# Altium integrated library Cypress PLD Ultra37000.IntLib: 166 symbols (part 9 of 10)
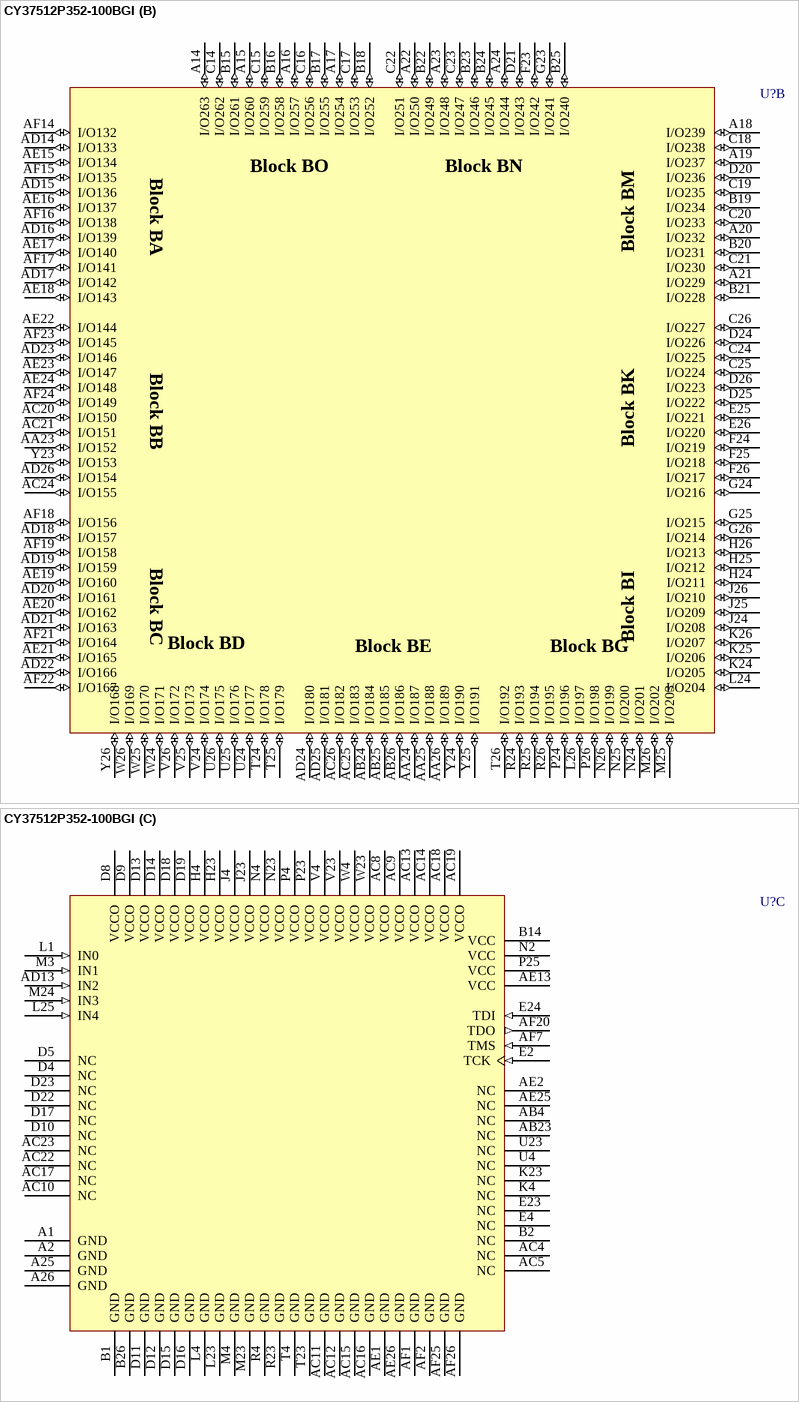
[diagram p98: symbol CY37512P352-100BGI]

## CY37512P352-100BGI
designator U?
Ultra37000 5V, ISR High-Performance CPLD
footprint BG352 (BGA, 388-Leads, Body 35x35mm, Pitch 1.27mm)
3D model CY37512P352-BG352 (388-Ball Ball Grid Array 1.27 mm Pitch)
part A pins: A3 I/O19 (io), A4 I/O15 (io), A5 I/O13 (io), A6 I/O34 (io), A7 I/O31 (io), A8 I/O28 (io), A9 I/O25 (io), A10 I/O10 (io), A11 I/O7 (io), A12 I/O4 (io), A13 I/O1 (io), AA1 I/O74 (io), AA2 I/O75 (io), AA3 I/O76 (io), AA4 I/O111 (io), AB1 I/O77 (io), AB2 I/O78 (io), AB3 I/O79 (io), AC1 I/O81 (io), AC2 I/O80 (io), AC3 I/O108 (io), AC6 I/O112 (io), AC7 I/O113 (io), AD1 I/O109 (io), AD2 I/O82 (io), AD3 I/O83 (io), AD4 I/O117 (io), AD5 I/O97 (io), AD6 I/O100 (io), AD7 I/O102 (io), AD8 I/O105 (io), AD9 I/O120 (io), AD10 I/O123 (io), AD11 I/O126 (io), AD12 I/O129 (io), AE3 I/O115 (io), AE4 I/O116 (io), AE5 I/O119 (io), AE6 I/O98 (io), AE7 I/O101 (io), AE8 I/O103 (io), AE9 I/O106 (io), AE10 I/O121 (io), AE11 I/O124 (io), AE12 I/O127 (io), AE14 I/O130 (io), AF3 I/O114 (io), AF4 I/O118 (io), AF5 I/O96 (io), AF6 I/O99 (io), AF8 I/O104 (io), AF9 I/O107 (io), AF10 I/O122 (io), AF11 I/O125 (io), AF12 I/O128 (io), AF13 I/O131 (io), B3 I/O18 (io), B4 I/O17 (io), B5 I/O14 (io), B6 I/O35 (io), B7 I/O32 (io), B8 I/O29 (io), B9 I/O26 (io), B10 I/O11 (io), B11 I/O8 (io), B12 I/O5 (io), B13 I/O2 (io), C1 I/O23 (io), C2 I/O38 (io), C3 I/O37 (io), C4 I/O16 (io), C5 I/O12 (io), C6 I/O33 (io), C7 I/O30 (io), C8 I/O27 (io), C9 I/O24 (io), C10 I/O9 (io), C11 I/O6 (io), C12 I/O3 (io), C13 I/O0 (io), D1 I/O39 (io), D2 I/O40 (io), D3 I/O36 (io), D6 I/O21 (io), D7 I/O20 (io), E1 I/O42 (io), E3 I/O41 (io), F1 I/O45 (io), F2 I/O44 (io), F3 I/O43 (io), F4 I/O22 (io), G1 I/O48 (io), G2 I/O47 (io), G3 I/O46 (io), G4 I/O63 (io), H1 I/O49 (io), H2 I/O50 (io), H3 I/O51 (io), J1 I/O52 (io), J2 I/O53 (io), J3 I/O54 (io), K1 I/O55 (io), K2 I/O56 (io), K3 I/O57 (io), L2 I/O59 (io), L3 I/O58 (io), M1 I/O61 (io), M2 I/O60 (io), N1 I/O64 (io), N3 I/O62 (io), P1 I/O65 (io), P2 I/O66 (io), P3 I/O67 (io), R1 I/O68 (io), R2 I/O69 (io), R3 I/O70 (io), T1 I/O71 (io), T2 I/O84 (io), T3 I/O85 (io), U1 I/O88 (io), U2 I/O87 (io), U3 I/O86 (io), V1 I/O91 (io), V2 I/O90 (io), V3 I/O89 (io), W1 I/O94 (io), W2 I/O93 (io), W3 I/O92 (io), Y1 I/O95 (io), Y2 I/O72 (io), Y3 I/O73 (io), Y4 I/O110 (io)
part B pins: A14 I/O263 (io), A15 I/O260 (io), A16 I/O257 (io), A17 I/O254 (io), A18 I/O239 (io), A19 I/O237 (io), A20 I/O232 (io), A21 I/O229 (io), A22 I/O250 (io), A23 I/O248 (io), A24 I/O244 (io), AA23 I/O152 (io), AA24 I/O187 (io), AA25 I/O188 (io), AA26 I/O189 (io), AB24 I/O184 (io), AB25 I/O185 (io), AB26 I/O186 (io), AC20 I/O150 (io), AC21 I/O151 (io), AC24 I/O155 (io), AC25 I/O183 (io), AC26 I/O182 (io), AD14 I/O133 (io), AD15 I/O136 (io), AD16 I/O139 (io), AD17 I/O142 (io), AD18 I/O157 (io), AD19 I/O159 (io), AD20 I/O161 (io), AD21 I/O163 (io), AD22 I/O166 (io), AD23 I/O146 (io), AD24 I/O180 (io), AD25 I/O181 (io), AD26 I/O154 (io), AE15 I/O134 (io), AE16 I/O137 (io), AE17 I/O140 (io), AE18 I/O143 (io), AE19 I/O160 (io), AE20 I/O162 (io), AE21 I/O165 (io), AE22 I/O144 (io), AE23 I/O147 (io), AE24 I/O148 (io), AF14 I/O132 (io), AF15 I/O135 (io), AF16 I/O138 (io), AF17 I/O141 (io), AF18 I/O156 (io), AF19 I/O158 (io), AF21 I/O164 (io), AF22 I/O167 (io), AF23 I/O145 (io), AF24 I/O149 (io), B15 I/O261 (io), B16 I/O258 (io), B17 I/O255 (io), B18 I/O252 (io), B19 I/O234 (io), B20 I/O231 (io), B21 I/O228 (io), B22 I/O249 (io), B23 I/O246 (io), B24 I/O245 (io), B25 I/O240 (io), C14 I/O262 (io), C15 I/O259 (io), C16 I/O256 (io), C17 I/O253 (io), C18 I/O238 (io), C19 I/O235 (io), C20 I/O233 (io), C21 I/O230 (io), C22 I/O251 (io), C23 I/O247 (io), C24 I/O225 (io), C25 I/O224 (io), C26 I/O227 (io), D20 I/O236 (io), D21 I/O243 (io), D24 I/O226 (io), D25 I/O222 (io), D26 I/O223 (io), E25 I/O221 (io), E26 I/O220 (io), F23 I/O242 (io), F24 I/O219 (io), F25 I/O218 (io), F26 I/O217 (io), G23 I/O241 (io), G24 I/O216 (io), G25 I/O215 (io), G26 I/O214 (io), H24 I/O211 (io), H25 I/O212 (io), H26 I/O213 (io), J24 I/O208 (io), J25 I/O209 (io), J26 I/O210 (io), K24 I/O205 (io), K25 I/O206 (io), K26 I/O207 (io), L24 I/O204 (io), L26 I/O197 (io), M25 I/O203 (io), M26 I/O202 (io), N24 I/O201 (io), N25 I/O200 (io), N26 I/O199 (io), P24 I/O196 (io), P26 I/O198 (io), R24 I/O193 (io), R25 I/O194 (io), R26 I/O195 (io), T24 I/O178 (io), T25 I/O179 (io), T26 I/O192 (io), U24 I/O177 (io), U25 I/O176 (io), U26 I/O175 (io), V24 I/O174 (io), V25 I/O173 (io), V26 I/O172 (io), W24 I/O171 (io), W25 I/O170 (io), W26 I/O169 (io), Y23 I/O153 (io), Y24 I/O190 (io), Y25 I/O191 (io), Y26 I/O168 (io)
part C pins: A1 GND (power), A2 GND (power), A25 GND (power), A26 GND (power), AB4 NC, AB23 NC, AC4 NC, AC5 NC, AC8 VCCO (power), AC9 VCCO (power), AC10 NC, AC11 GND (power), AC12 GND (power), AC13 VCCO (power), AC14 VCCO (power), AC15 GND (power), AC16 GND (power), AC17 NC, AC18 VCCO (power), AC19 VCCO (power), AC22 NC, AC23 NC, AD13 IN2 (in), AE1 GND (power), AE2 NC, AE13 VCC (power), AE25 NC, AE26 GND (power), AF1 GND (power), AF2 GND (power), AF7 TMS (in), AF20 TDO (out), AF25 GND (power), AF26 GND (power), B1 GND (power), B2 NC, B14 VCC (power), B26 GND (power), D4 NC, D5 NC, D8 VCCO (power), D9 VCCO (power), D10 NC, D11 GND (power), D12 GND (power), D13 VCCO (power), D14 VCCO (power), D15 GND (power), D16 GND (power), D17 NC, D18 VCCO (power), D19 VCCO (power), D22 NC, D23 NC, E2 TCK (in), E4 NC, E23 NC, E24 TDI (in), H4 VCCO (power), H23 VCCO (power), J4 VCCO (power), J23 VCCO (power), K4 NC, K23 NC, L1 IN0 (in), L4 GND (power), L23 GND (power), L25 IN4 (in), M3 IN1 (in), M4 GND (power), M23 GND (power), M24 IN3 (in), N2 VCC (power), N4 VCCO (power), N23 VCCO (power), P4 VCCO (power), P23 VCCO (power), P25 VCC (power), R4 GND (power), R23 GND (power), T4 GND (power), T23 GND (power), U4 NC, U23 NC, V4 VCCO (power), V23 VCCO (power), W4 VCCO (power), W23 VCCO (power)

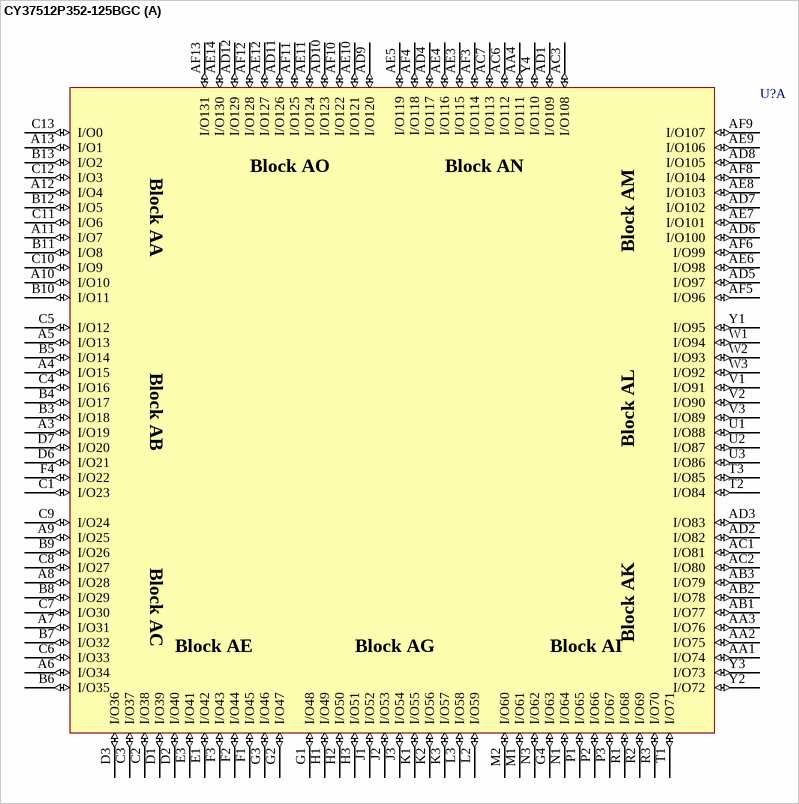
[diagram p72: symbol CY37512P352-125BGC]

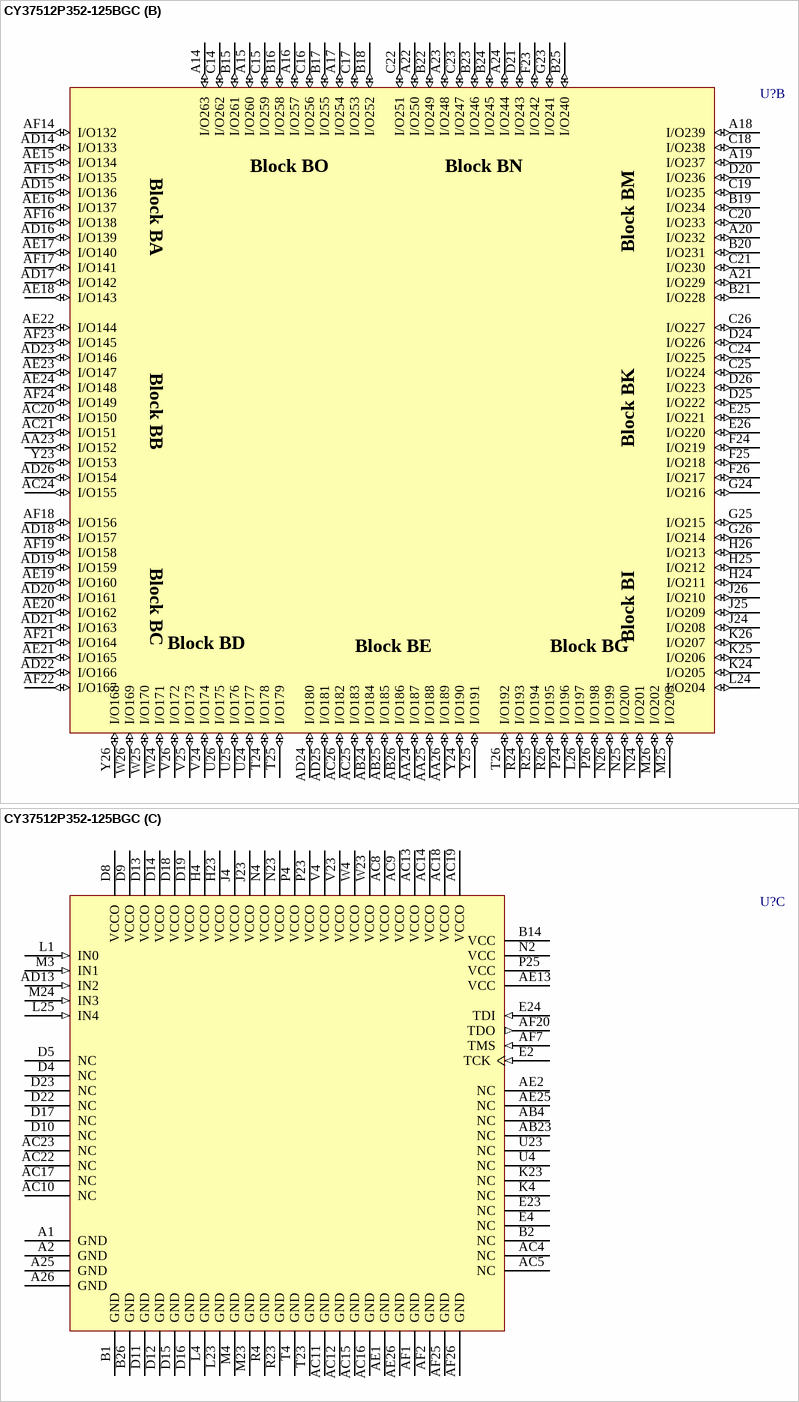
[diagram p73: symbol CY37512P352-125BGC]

## CY37512P352-125BGC
designator U?
Ultra37000 5V, ISR High-Performance CPLD
footprint BG352 (BGA, 388-Leads, Body 35x35mm, Pitch 1.27mm)
3D model CY37512P352-BG352 (388-Ball Ball Grid Array 1.27 mm Pitch)
part A pins: A3 I/O19 (io), A4 I/O15 (io), A5 I/O13 (io), A6 I/O34 (io), A7 I/O31 (io), A8 I/O28 (io), A9 I/O25 (io), A10 I/O10 (io), A11 I/O7 (io), A12 I/O4 (io), A13 I/O1 (io), AA1 I/O74 (io), AA2 I/O75 (io), AA3 I/O76 (io), AA4 I/O111 (io), AB1 I/O77 (io), AB2 I/O78 (io), AB3 I/O79 (io), AC1 I/O81 (io), AC2 I/O80 (io), AC3 I/O108 (io), AC6 I/O112 (io), AC7 I/O113 (io), AD1 I/O109 (io), AD2 I/O82 (io), AD3 I/O83 (io), AD4 I/O117 (io), AD5 I/O97 (io), AD6 I/O100 (io), AD7 I/O102 (io), AD8 I/O105 (io), AD9 I/O120 (io), AD10 I/O123 (io), AD11 I/O126 (io), AD12 I/O129 (io), AE3 I/O115 (io), AE4 I/O116 (io), AE5 I/O119 (io), AE6 I/O98 (io), AE7 I/O101 (io), AE8 I/O103 (io), AE9 I/O106 (io), AE10 I/O121 (io), AE11 I/O124 (io), AE12 I/O127 (io), AE14 I/O130 (io), AF3 I/O114 (io), AF4 I/O118 (io), AF5 I/O96 (io), AF6 I/O99 (io), AF8 I/O104 (io), AF9 I/O107 (io), AF10 I/O122 (io), AF11 I/O125 (io), AF12 I/O128 (io), AF13 I/O131 (io), B3 I/O18 (io), B4 I/O17 (io), B5 I/O14 (io), B6 I/O35 (io), B7 I/O32 (io), B8 I/O29 (io), B9 I/O26 (io), B10 I/O11 (io), B11 I/O8 (io), B12 I/O5 (io), B13 I/O2 (io), C1 I/O23 (io), C2 I/O38 (io), C3 I/O37 (io), C4 I/O16 (io), C5 I/O12 (io), C6 I/O33 (io), C7 I/O30 (io), C8 I/O27 (io), C9 I/O24 (io), C10 I/O9 (io), C11 I/O6 (io), C12 I/O3 (io), C13 I/O0 (io), D1 I/O39 (io), D2 I/O40 (io), D3 I/O36 (io), D6 I/O21 (io), D7 I/O20 (io), E1 I/O42 (io), E3 I/O41 (io), F1 I/O45 (io), F2 I/O44 (io), F3 I/O43 (io), F4 I/O22 (io), G1 I/O48 (io), G2 I/O47 (io), G3 I/O46 (io), G4 I/O63 (io), H1 I/O49 (io), H2 I/O50 (io), H3 I/O51 (io), J1 I/O52 (io), J2 I/O53 (io), J3 I/O54 (io), K1 I/O55 (io), K2 I/O56 (io), K3 I/O57 (io), L2 I/O59 (io), L3 I/O58 (io), M1 I/O61 (io), M2 I/O60 (io), N1 I/O64 (io), N3 I/O62 (io), P1 I/O65 (io), P2 I/O66 (io), P3 I/O67 (io), R1 I/O68 (io), R2 I/O69 (io), R3 I/O70 (io), T1 I/O71 (io), T2 I/O84 (io), T3 I/O85 (io), U1 I/O88 (io), U2 I/O87 (io), U3 I/O86 (io), V1 I/O91 (io), V2 I/O90 (io), V3 I/O89 (io), W1 I/O94 (io), W2 I/O93 (io), W3 I/O92 (io), Y1 I/O95 (io), Y2 I/O72 (io), Y3 I/O73 (io), Y4 I/O110 (io)
part B pins: A14 I/O263 (io), A15 I/O260 (io), A16 I/O257 (io), A17 I/O254 (io), A18 I/O239 (io), A19 I/O237 (io), A20 I/O232 (io), A21 I/O229 (io), A22 I/O250 (io), A23 I/O248 (io), A24 I/O244 (io), AA23 I/O152 (io), AA24 I/O187 (io), AA25 I/O188 (io), AA26 I/O189 (io), AB24 I/O184 (io), AB25 I/O185 (io), AB26 I/O186 (io), AC20 I/O150 (io), AC21 I/O151 (io), AC24 I/O155 (io), AC25 I/O183 (io), AC26 I/O182 (io), AD14 I/O133 (io), AD15 I/O136 (io), AD16 I/O139 (io), AD17 I/O142 (io), AD18 I/O157 (io), AD19 I/O159 (io), AD20 I/O161 (io), AD21 I/O163 (io), AD22 I/O166 (io), AD23 I/O146 (io), AD24 I/O180 (io), AD25 I/O181 (io), AD26 I/O154 (io), AE15 I/O134 (io), AE16 I/O137 (io), AE17 I/O140 (io), AE18 I/O143 (io), AE19 I/O160 (io), AE20 I/O162 (io), AE21 I/O165 (io), AE22 I/O144 (io), AE23 I/O147 (io), AE24 I/O148 (io), AF14 I/O132 (io), AF15 I/O135 (io), AF16 I/O138 (io), AF17 I/O141 (io), AF18 I/O156 (io), AF19 I/O158 (io), AF21 I/O164 (io), AF22 I/O167 (io), AF23 I/O145 (io), AF24 I/O149 (io), B15 I/O261 (io), B16 I/O258 (io), B17 I/O255 (io), B18 I/O252 (io), B19 I/O234 (io), B20 I/O231 (io), B21 I/O228 (io), B22 I/O249 (io), B23 I/O246 (io), B24 I/O245 (io), B25 I/O240 (io), C14 I/O262 (io), C15 I/O259 (io), C16 I/O256 (io), C17 I/O253 (io), C18 I/O238 (io), C19 I/O235 (io), C20 I/O233 (io), C21 I/O230 (io), C22 I/O251 (io), C23 I/O247 (io), C24 I/O225 (io), C25 I/O224 (io), C26 I/O227 (io), D20 I/O236 (io), D21 I/O243 (io), D24 I/O226 (io), D25 I/O222 (io), D26 I/O223 (io), E25 I/O221 (io), E26 I/O220 (io), F23 I/O242 (io), F24 I/O219 (io), F25 I/O218 (io), F26 I/O217 (io), G23 I/O241 (io), G24 I/O216 (io), G25 I/O215 (io), G26 I/O214 (io), H24 I/O211 (io), H25 I/O212 (io), H26 I/O213 (io), J24 I/O208 (io), J25 I/O209 (io), J26 I/O210 (io), K24 I/O205 (io), K25 I/O206 (io), K26 I/O207 (io), L24 I/O204 (io), L26 I/O197 (io), M25 I/O203 (io), M26 I/O202 (io), N24 I/O201 (io), N25 I/O200 (io), N26 I/O199 (io), P24 I/O196 (io), P26 I/O198 (io), R24 I/O193 (io), R25 I/O194 (io), R26 I/O195 (io), T24 I/O178 (io), T25 I/O179 (io), T26 I/O192 (io), U24 I/O177 (io), U25 I/O176 (io), U26 I/O175 (io), V24 I/O174 (io), V25 I/O173 (io), V26 I/O172 (io), W24 I/O171 (io), W25 I/O170 (io), W26 I/O169 (io), Y23 I/O153 (io), Y24 I/O190 (io), Y25 I/O191 (io), Y26 I/O168 (io)
part C pins: A1 GND (power), A2 GND (power), A25 GND (power), A26 GND (power), AB4 NC, AB23 NC, AC4 NC, AC5 NC, AC8 VCCO (power), AC9 VCCO (power), AC10 NC, AC11 GND (power), AC12 GND (power), AC13 VCCO (power), AC14 VCCO (power), AC15 GND (power), AC16 GND (power), AC17 NC, AC18 VCCO (power), AC19 VCCO (power), AC22 NC, AC23 NC, AD13 IN2 (in), AE1 GND (power), AE2 NC, AE13 VCC (power), AE25 NC, AE26 GND (power), AF1 GND (power), AF2 GND (power), AF7 TMS (in), AF20 TDO (out), AF25 GND (power), AF26 GND (power), B1 GND (power), B2 NC, B14 VCC (power), B26 GND (power), D4 NC, D5 NC, D8 VCCO (power), D9 VCCO (power), D10 NC, D11 GND (power), D12 GND (power), D13 VCCO (power), D14 VCCO (power), D15 GND (power), D16 GND (power), D17 NC, D18 VCCO (power), D19 VCCO (power), D22 NC, D23 NC, E2 TCK (in), E4 NC, E23 NC, E24 TDI (in), H4 VCCO (power), H23 VCCO (power), J4 VCCO (power), J23 VCCO (power), K4 NC, K23 NC, L1 IN0 (in), L4 GND (power), L23 GND (power), L25 IN4 (in), M3 IN1 (in), M4 GND (power), M23 GND (power), M24 IN3 (in), N2 VCC (power), N4 VCCO (power), N23 VCCO (power), P4 VCCO (power), P23 VCCO (power), P25 VCC (power), R4 GND (power), R23 GND (power), T4 GND (power), T23 GND (power), U4 NC, U23 NC, V4 VCCO (power), V23 VCCO (power), W4 VCCO (power), W23 VCCO (power)

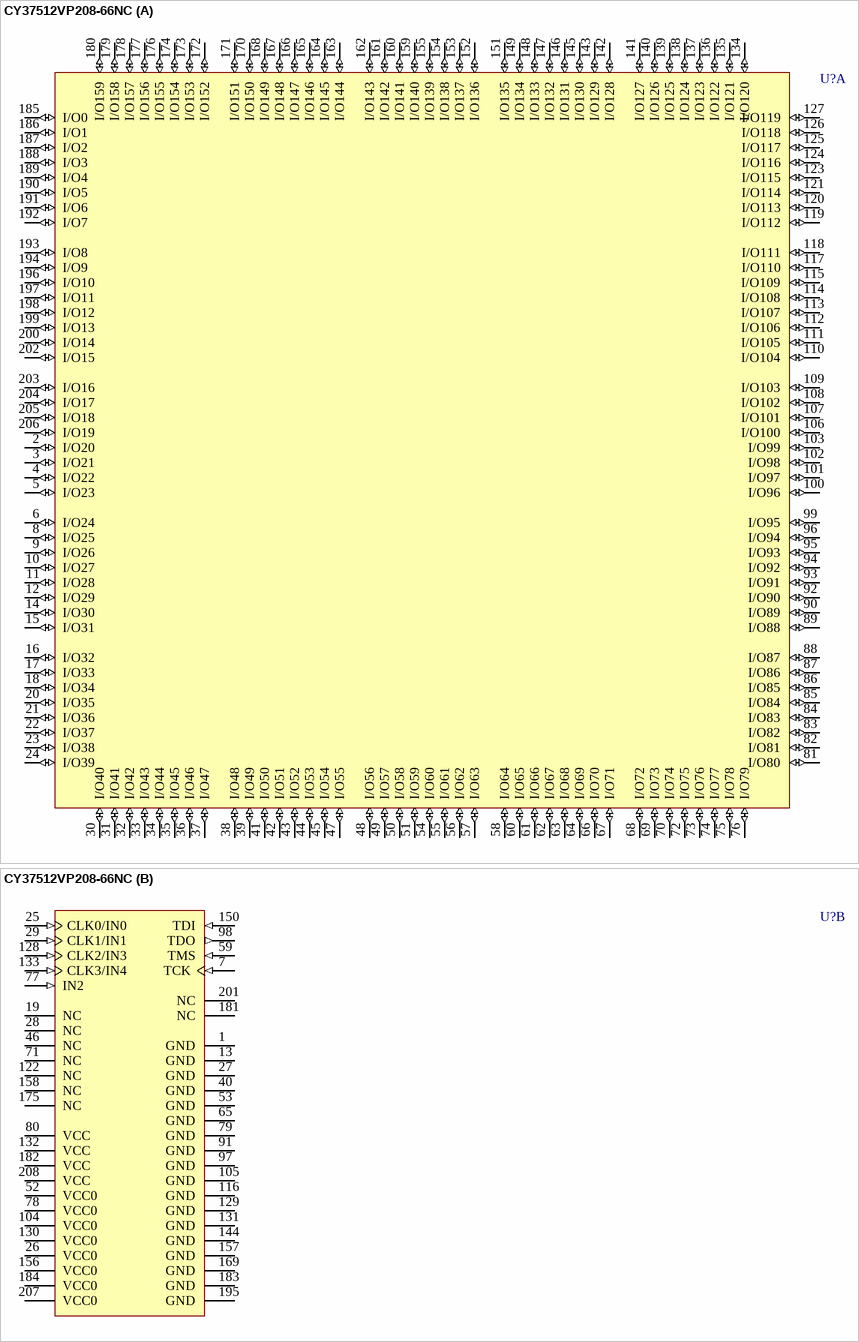
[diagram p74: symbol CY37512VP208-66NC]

## CY37512VP208-66NC
designator U?
Ultra37000 3.3V, ISR High-Performance CPLD
footprint N208_N (Shrink QFP, 208-Leads, Body 28x28mm, Pitch 0.5mm, IPC Medium Density)
footprint N208_L (Shrink QFP, 208-Leads, Body 28x28mm, Pitch 0.5mm, IPC High Density)
footprint N208_M (Shrink QFP, 208-Leads, Body 28x28mm, Pitch 0.5mm, IPC Low Density)
3D model CY37512VP208-N208 (208-Pin Plastic Shrink Quad Flat Pack 0.5 mm Pitch)
part A pins: 2 I/O20 (io), 3 I/O21 (io), 4 I/O22 (io), 5 I/O23 (io), 6 I/O24 (io), 8 I/O25 (io), 9 I/O26 (io), 10 I/O27 (io), 11 I/O28 (io), 12 I/O29 (io), 14 I/O30 (io), 15 I/O31 (io), 16 I/O32 (io), 17 I/O33 (io), 18 I/O34 (io), 20 I/O35 (io), 21 I/O36 (io), 22 I/O37 (io), 23 I/O38 (io), 24 I/O39 (io), 30 I/O40 (io), 31 I/O41 (io), 32 I/O42 (io), 33 I/O43 (io), 34 I/O44 (io), 35 I/O45 (io), 36 I/O46 (io), 37 I/O47 (io), 38 I/O48 (io), 39 I/O49 (io), 41 I/O50 (io), 42 I/O51 (io), 43 I/O52 (io), 44 I/O53 (io), 45 I/O54 (io), 47 I/O55 (io), 48 I/O56 (io), 49 I/O57 (io), 50 I/O58 (io), 51 I/O59 (io), 54 I/O60 (io), 55 I/O61 (io), 56 I/O62 (io), 57 I/O63 (io), 58 I/O64 (io), 60 I/O65 (io), 61 I/O66 (io), 62 I/O67 (io), 63 I/O68 (io), 64 I/O69 (io), 66 I/O70 (io), 67 I/O71 (io), 68 I/O72 (io), 69 I/O73 (io), 70 I/O74 (io), 72 I/O75 (io), 73 I/O76 (io), 74 I/O77 (io), 75 I/O78 (io), 76 I/O79 (io), 81 I/O80 (io), 82 I/O81 (io), 83 I/O82 (io), 84 I/O83 (io), 85 I/O84 (io), 86 I/O85 (io), 87 I/O86 (io), 88 I/O87 (io), 89 I/O88 (io), 90 I/O89 (io), 92 I/O90 (io), 93 I/O91 (io), 94 I/O92 (io), 95 I/O93 (io), 96 I/O94 (io), 99 I/O95 (io), 100 I/O96 (io), 101 I/O97 (io), 102 I/O98 (io), 103 I/O99 (io), 106 I/O100 (io), 107 I/O101 (io), 108 I/O102 (io), 109 I/O103 (io), 110 I/O104 (io), 111 I/O105 (io), 112 I/O106 (io), 113 I/O107 (io), 114 I/O108 (io), 115 I/O109 (io), 117 I/O110 (io), 118 I/O111 (io), 119 I/O112 (io), 120 I/O113 (io), 121 I/O114 (io), 123 I/O115 (io), 124 I/O116 (io), 125 I/O117 (io), 126 I/O118 (io), 127 I/O119 (io), 134 I/O120 (io), 135 I/O121 (io), 136 I/O122 (io), 137 I/O123 (io), 138 I/O124 (io), 139 I/O125 (io), 140 I/O126 (io), 141 I/O127 (io), 142 I/O128 (io), 143 I/O129 (io), 145 I/O130 (io), 146 I/O131 (io), 147 I/O132 (io), 148 I/O133 (io), 149 I/O134 (io), 151 I/O135 (io), 152 I/O136 (io), 153 I/O137 (io), 154 I/O138 (io), 155 I/O139 (io), 159 I/O140 (io), 160 I/O141 (io), 161 I/O142 (io), 162 I/O143 (io), 163 I/O144 (io), 164 I/O145 (io), 165 I/O146 (io), 166 I/O147 (io), 167 I/O148 (io), 168 I/O149 (io), 170 I/O150 (io), 171 I/O151 (io), 172 I/O152 (io), 173 I/O153 (io), 174 I/O154 (io), 176 I/O155 (io), 177 I/O156 (io), 178 I/O157 (io), 179 I/O158 (io), 180 I/O159 (io), 185 I/O0 (io), 186 I/O1 (io), 187 I/O2 (io), 188 I/O3 (io), 189 I/O4 (io), 190 I/O5 (io), 191 I/O6 (io), 192 I/O7 (io), 193 I/O8 (io), 194 I/O9 (io), 196 I/O10 (io), 197 I/O11 (io), 198 I/O12 (io), 199 I/O13 (io), 200 I/O14 (io), 202 I/O15 (io), 203 I/O16 (io), 204 I/O17 (io), 205 I/O18 (io), 206 I/O19 (io)
part B pins: 1 GND (power), 7 TCK (in), 13 GND (power), 19 NC, 25 CLK0/IN0 (in), 26 VCC0 (power), 27 GND (power), 28 NC, 29 CLK1/IN1 (in), 40 GND (power), 46 NC, 52 VCC0 (power), 53 GND (power), 59 TMS (in), 65 GND (power), 71 NC, 77 IN2 (in), 78 VCC0 (power), 79 GND (power), 80 VCC (power), 91 GND (power), 97 GND (power), 98 TDO (out), 104 VCC0 (power), 105 GND (power), 116 GND (power), 122 NC, 128 CLK2/IN3 (in), 129 GND (power), 130 VCC0 (power), 131 GND (power), 132 VCC (power), 133 CLK3/IN4 (in), 144 GND (power), 150 TDI (in), 156 VCC0 (power), 157 GND (power), 158 NC, 169 GND (power), 175 NC, 181 NC, 182 VCC (power), 183 GND (power), 184 VCC0 (power), 195 GND (power), 201 NC, 207 VCC0 (power), 208 VCC (power)

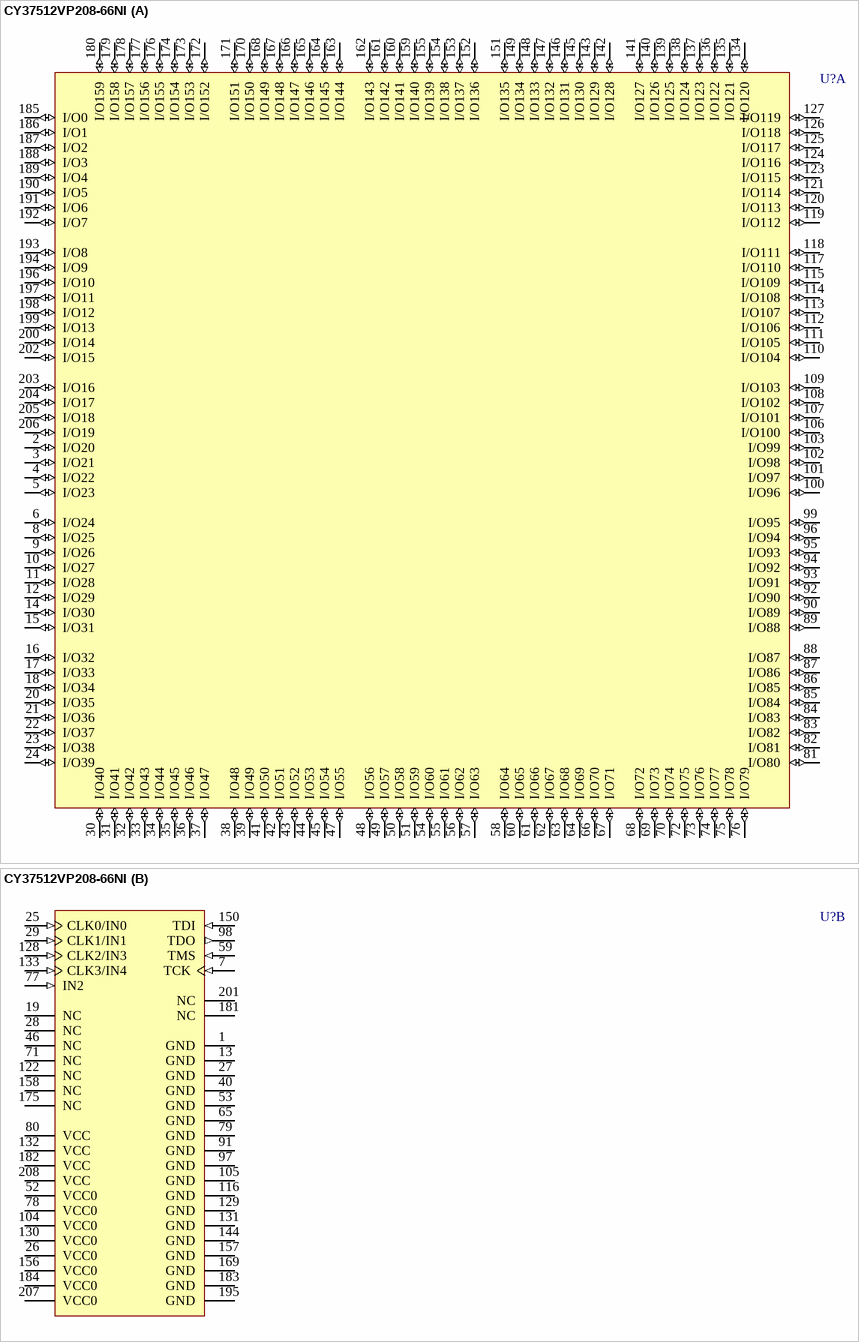
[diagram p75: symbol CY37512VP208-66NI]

## CY37512VP208-66NI
designator U?
Ultra37000 3.3V, ISR High-Performance CPLD
footprint N208_N (Shrink QFP, 208-Leads, Body 28x28mm, Pitch 0.5mm, IPC Medium Density)
footprint N208_L (Shrink QFP, 208-Leads, Body 28x28mm, Pitch 0.5mm, IPC High Density)
footprint N208_M (Shrink QFP, 208-Leads, Body 28x28mm, Pitch 0.5mm, IPC Low Density)
3D model CY37512VP208-N208 (208-Pin Plastic Shrink Quad Flat Pack 0.5 mm Pitch)
part A pins: 2 I/O20 (io), 3 I/O21 (io), 4 I/O22 (io), 5 I/O23 (io), 6 I/O24 (io), 8 I/O25 (io), 9 I/O26 (io), 10 I/O27 (io), 11 I/O28 (io), 12 I/O29 (io), 14 I/O30 (io), 15 I/O31 (io), 16 I/O32 (io), 17 I/O33 (io), 18 I/O34 (io), 20 I/O35 (io), 21 I/O36 (io), 22 I/O37 (io), 23 I/O38 (io), 24 I/O39 (io), 30 I/O40 (io), 31 I/O41 (io), 32 I/O42 (io), 33 I/O43 (io), 34 I/O44 (io), 35 I/O45 (io), 36 I/O46 (io), 37 I/O47 (io), 38 I/O48 (io), 39 I/O49 (io), 41 I/O50 (io), 42 I/O51 (io), 43 I/O52 (io), 44 I/O53 (io), 45 I/O54 (io), 47 I/O55 (io), 48 I/O56 (io), 49 I/O57 (io), 50 I/O58 (io), 51 I/O59 (io), 54 I/O60 (io), 55 I/O61 (io), 56 I/O62 (io), 57 I/O63 (io), 58 I/O64 (io), 60 I/O65 (io), 61 I/O66 (io), 62 I/O67 (io), 63 I/O68 (io), 64 I/O69 (io), 66 I/O70 (io), 67 I/O71 (io), 68 I/O72 (io), 69 I/O73 (io), 70 I/O74 (io), 72 I/O75 (io), 73 I/O76 (io), 74 I/O77 (io), 75 I/O78 (io), 76 I/O79 (io), 81 I/O80 (io), 82 I/O81 (io), 83 I/O82 (io), 84 I/O83 (io), 85 I/O84 (io), 86 I/O85 (io), 87 I/O86 (io), 88 I/O87 (io), 89 I/O88 (io), 90 I/O89 (io), 92 I/O90 (io), 93 I/O91 (io), 94 I/O92 (io), 95 I/O93 (io), 96 I/O94 (io), 99 I/O95 (io), 100 I/O96 (io), 101 I/O97 (io), 102 I/O98 (io), 103 I/O99 (io), 106 I/O100 (io), 107 I/O101 (io), 108 I/O102 (io), 109 I/O103 (io), 110 I/O104 (io), 111 I/O105 (io), 112 I/O106 (io), 113 I/O107 (io), 114 I/O108 (io), 115 I/O109 (io), 117 I/O110 (io), 118 I/O111 (io), 119 I/O112 (io), 120 I/O113 (io), 121 I/O114 (io), 123 I/O115 (io), 124 I/O116 (io), 125 I/O117 (io), 126 I/O118 (io), 127 I/O119 (io), 134 I/O120 (io), 135 I/O121 (io), 136 I/O122 (io), 137 I/O123 (io), 138 I/O124 (io), 139 I/O125 (io), 140 I/O126 (io), 141 I/O127 (io), 142 I/O128 (io), 143 I/O129 (io), 145 I/O130 (io), 146 I/O131 (io), 147 I/O132 (io), 148 I/O133 (io), 149 I/O134 (io), 151 I/O135 (io), 152 I/O136 (io), 153 I/O137 (io), 154 I/O138 (io), 155 I/O139 (io), 159 I/O140 (io), 160 I/O141 (io), 161 I/O142 (io), 162 I/O143 (io), 163 I/O144 (io), 164 I/O145 (io), 165 I/O146 (io), 166 I/O147 (io), 167 I/O148 (io), 168 I/O149 (io), 170 I/O150 (io), 171 I/O151 (io), 172 I/O152 (io), 173 I/O153 (io), 174 I/O154 (io), 176 I/O155 (io), 177 I/O156 (io), 178 I/O157 (io), 179 I/O158 (io), 180 I/O159 (io), 185 I/O0 (io), 186 I/O1 (io), 187 I/O2 (io), 188 I/O3 (io), 189 I/O4 (io), 190 I/O5 (io), 191 I/O6 (io), 192 I/O7 (io), 193 I/O8 (io), 194 I/O9 (io), 196 I/O10 (io), 197 I/O11 (io), 198 I/O12 (io), 199 I/O13 (io), 200 I/O14 (io), 202 I/O15 (io), 203 I/O16 (io), 204 I/O17 (io), 205 I/O18 (io), 206 I/O19 (io)
part B pins: 1 GND (power), 7 TCK (in), 13 GND (power), 19 NC, 25 CLK0/IN0 (in), 26 VCC0 (power), 27 GND (power), 28 NC, 29 CLK1/IN1 (in), 40 GND (power), 46 NC, 52 VCC0 (power), 53 GND (power), 59 TMS (in), 65 GND (power), 71 NC, 77 IN2 (in), 78 VCC0 (power), 79 GND (power), 80 VCC (power), 91 GND (power), 97 GND (power), 98 TDO (out), 104 VCC0 (power), 105 GND (power), 116 GND (power), 122 NC, 128 CLK2/IN3 (in), 129 GND (power), 130 VCC0 (power), 131 GND (power), 132 VCC (power), 133 CLK3/IN4 (in), 144 GND (power), 150 TDI (in), 156 VCC0 (power), 157 GND (power), 158 NC, 169 GND (power), 175 NC, 181 NC, 182 VCC (power), 183 GND (power), 184 VCC0 (power), 195 GND (power), 201 NC, 207 VCC0 (power), 208 VCC (power)

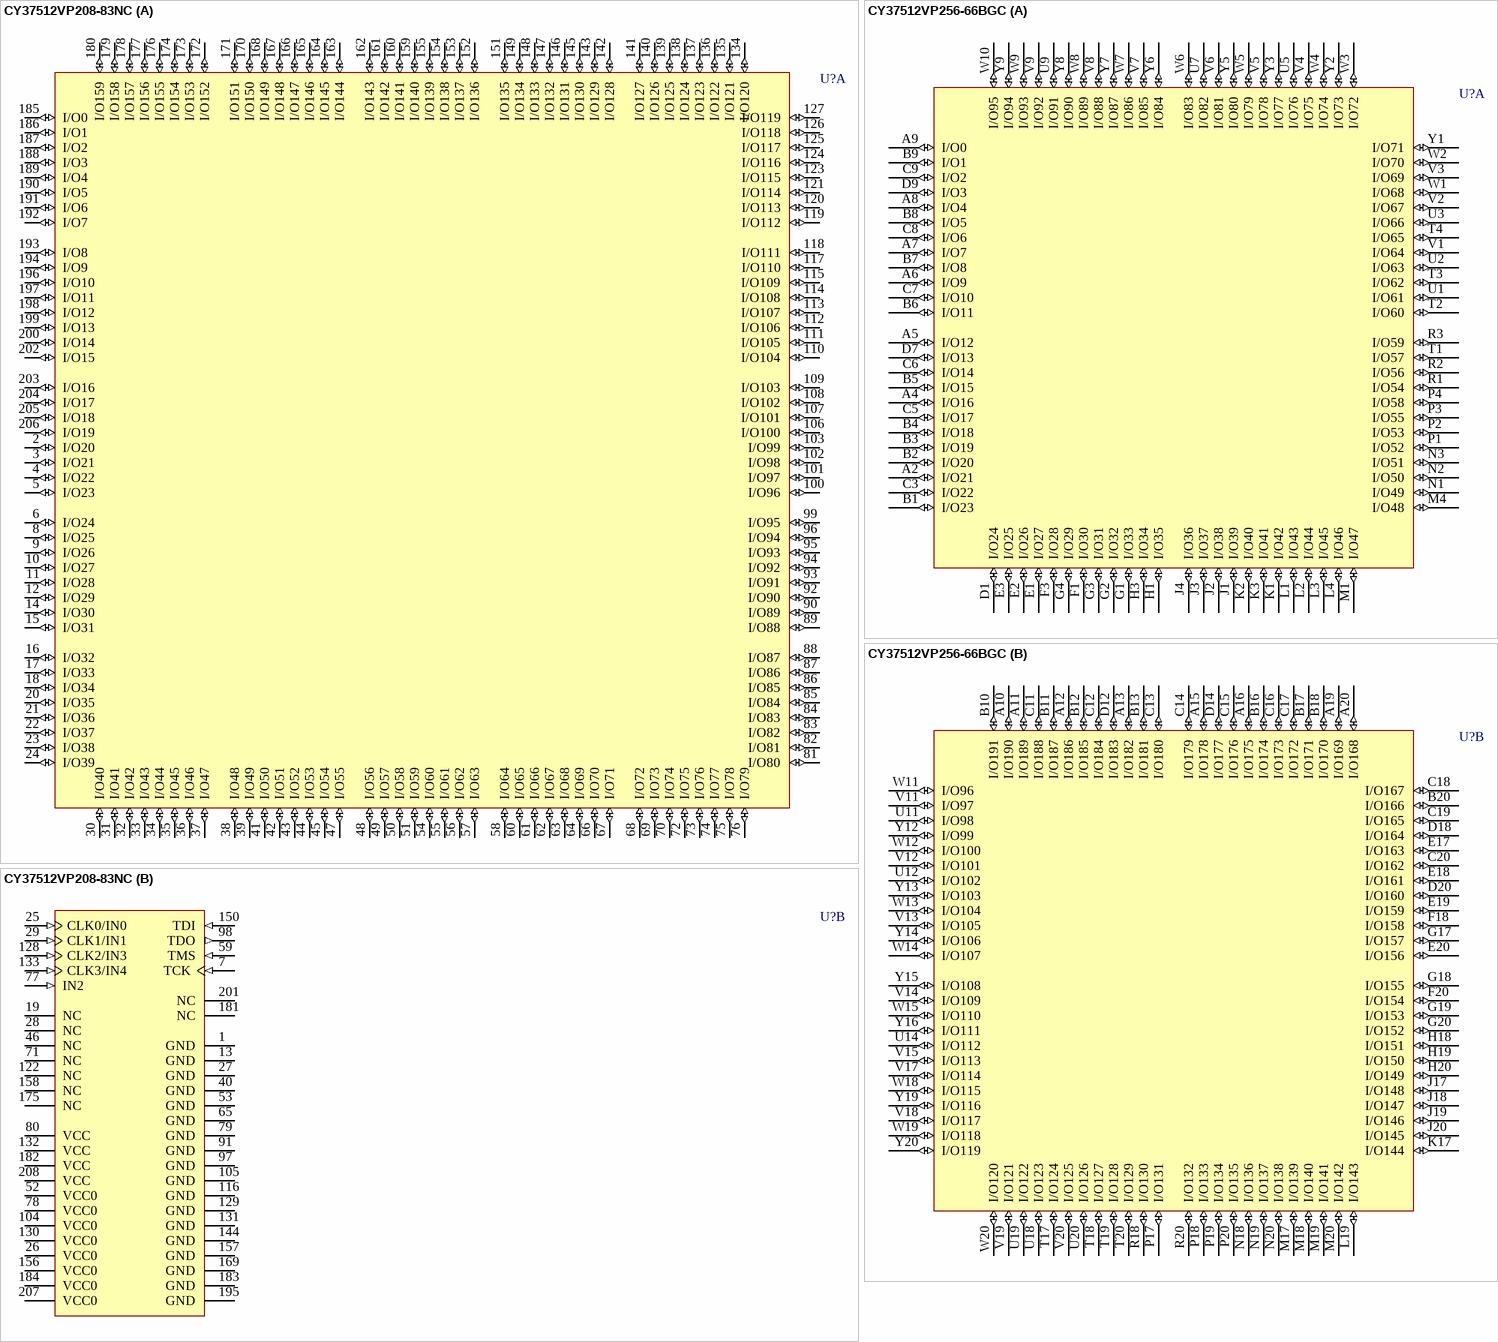
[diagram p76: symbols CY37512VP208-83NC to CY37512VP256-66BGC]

## CY37512VP208-83NC
designator U?
Ultra37000 3.3V, ISR High-Performance CPLD
footprint N208_N (Shrink QFP, 208-Leads, Body 28x28mm, Pitch 0.5mm, IPC Medium Density)
footprint N208_L (Shrink QFP, 208-Leads, Body 28x28mm, Pitch 0.5mm, IPC High Density)
footprint N208_M (Shrink QFP, 208-Leads, Body 28x28mm, Pitch 0.5mm, IPC Low Density)
3D model CY37512VP208-N208 (208-Pin Plastic Shrink Quad Flat Pack 0.5 mm Pitch)
part A pins: 2 I/O20 (io), 3 I/O21 (io), 4 I/O22 (io), 5 I/O23 (io), 6 I/O24 (io), 8 I/O25 (io), 9 I/O26 (io), 10 I/O27 (io), 11 I/O28 (io), 12 I/O29 (io), 14 I/O30 (io), 15 I/O31 (io), 16 I/O32 (io), 17 I/O33 (io), 18 I/O34 (io), 20 I/O35 (io), 21 I/O36 (io), 22 I/O37 (io), 23 I/O38 (io), 24 I/O39 (io), 30 I/O40 (io), 31 I/O41 (io), 32 I/O42 (io), 33 I/O43 (io), 34 I/O44 (io), 35 I/O45 (io), 36 I/O46 (io), 37 I/O47 (io), 38 I/O48 (io), 39 I/O49 (io), 41 I/O50 (io), 42 I/O51 (io), 43 I/O52 (io), 44 I/O53 (io), 45 I/O54 (io), 47 I/O55 (io), 48 I/O56 (io), 49 I/O57 (io), 50 I/O58 (io), 51 I/O59 (io), 54 I/O60 (io), 55 I/O61 (io), 56 I/O62 (io), 57 I/O63 (io), 58 I/O64 (io), 60 I/O65 (io), 61 I/O66 (io), 62 I/O67 (io), 63 I/O68 (io), 64 I/O69 (io), 66 I/O70 (io), 67 I/O71 (io), 68 I/O72 (io), 69 I/O73 (io), 70 I/O74 (io), 72 I/O75 (io), 73 I/O76 (io), 74 I/O77 (io), 75 I/O78 (io), 76 I/O79 (io), 81 I/O80 (io), 82 I/O81 (io), 83 I/O82 (io), 84 I/O83 (io), 85 I/O84 (io), 86 I/O85 (io), 87 I/O86 (io), 88 I/O87 (io), 89 I/O88 (io), 90 I/O89 (io), 92 I/O90 (io), 93 I/O91 (io), 94 I/O92 (io), 95 I/O93 (io), 96 I/O94 (io), 99 I/O95 (io), 100 I/O96 (io), 101 I/O97 (io), 102 I/O98 (io), 103 I/O99 (io), 106 I/O100 (io), 107 I/O101 (io), 108 I/O102 (io), 109 I/O103 (io), 110 I/O104 (io), 111 I/O105 (io), 112 I/O106 (io), 113 I/O107 (io), 114 I/O108 (io), 115 I/O109 (io), 117 I/O110 (io), 118 I/O111 (io), 119 I/O112 (io), 120 I/O113 (io), 121 I/O114 (io), 123 I/O115 (io), 124 I/O116 (io), 125 I/O117 (io), 126 I/O118 (io), 127 I/O119 (io), 134 I/O120 (io), 135 I/O121 (io), 136 I/O122 (io), 137 I/O123 (io), 138 I/O124 (io), 139 I/O125 (io), 140 I/O126 (io), 141 I/O127 (io), 142 I/O128 (io), 143 I/O129 (io), 145 I/O130 (io), 146 I/O131 (io), 147 I/O132 (io), 148 I/O133 (io), 149 I/O134 (io), 151 I/O135 (io), 152 I/O136 (io), 153 I/O137 (io), 154 I/O138 (io), 155 I/O139 (io), 159 I/O140 (io), 160 I/O141 (io), 161 I/O142 (io), 162 I/O143 (io), 163 I/O144 (io), 164 I/O145 (io), 165 I/O146 (io), 166 I/O147 (io), 167 I/O148 (io), 168 I/O149 (io), 170 I/O150 (io), 171 I/O151 (io), 172 I/O152 (io), 173 I/O153 (io), 174 I/O154 (io), 176 I/O155 (io), 177 I/O156 (io), 178 I/O157 (io), 179 I/O158 (io), 180 I/O159 (io), 185 I/O0 (io), 186 I/O1 (io), 187 I/O2 (io), 188 I/O3 (io), 189 I/O4 (io), 190 I/O5 (io), 191 I/O6 (io), 192 I/O7 (io), 193 I/O8 (io), 194 I/O9 (io), 196 I/O10 (io), 197 I/O11 (io), 198 I/O12 (io), 199 I/O13 (io), 200 I/O14 (io), 202 I/O15 (io), 203 I/O16 (io), 204 I/O17 (io), 205 I/O18 (io), 206 I/O19 (io)
part B pins: 1 GND (power), 7 TCK (in), 13 GND (power), 19 NC, 25 CLK0/IN0 (in), 26 VCC0 (power), 27 GND (power), 28 NC, 29 CLK1/IN1 (in), 40 GND (power), 46 NC, 52 VCC0 (power), 53 GND (power), 59 TMS (in), 65 GND (power), 71 NC, 77 IN2 (in), 78 VCC0 (power), 79 GND (power), 80 VCC (power), 91 GND (power), 97 GND (power), 98 TDO (out), 104 VCC0 (power), 105 GND (power), 116 GND (power), 122 NC, 128 CLK2/IN3 (in), 129 GND (power), 130 VCC0 (power), 131 GND (power), 132 VCC (power), 133 CLK3/IN4 (in), 144 GND (power), 150 TDI (in), 156 VCC0 (power), 157 GND (power), 158 NC, 169 GND (power), 175 NC, 181 NC, 182 VCC (power), 183 GND (power), 184 VCC0 (power), 195 GND (power), 201 NC, 207 VCC0 (power), 208 VCC (power)

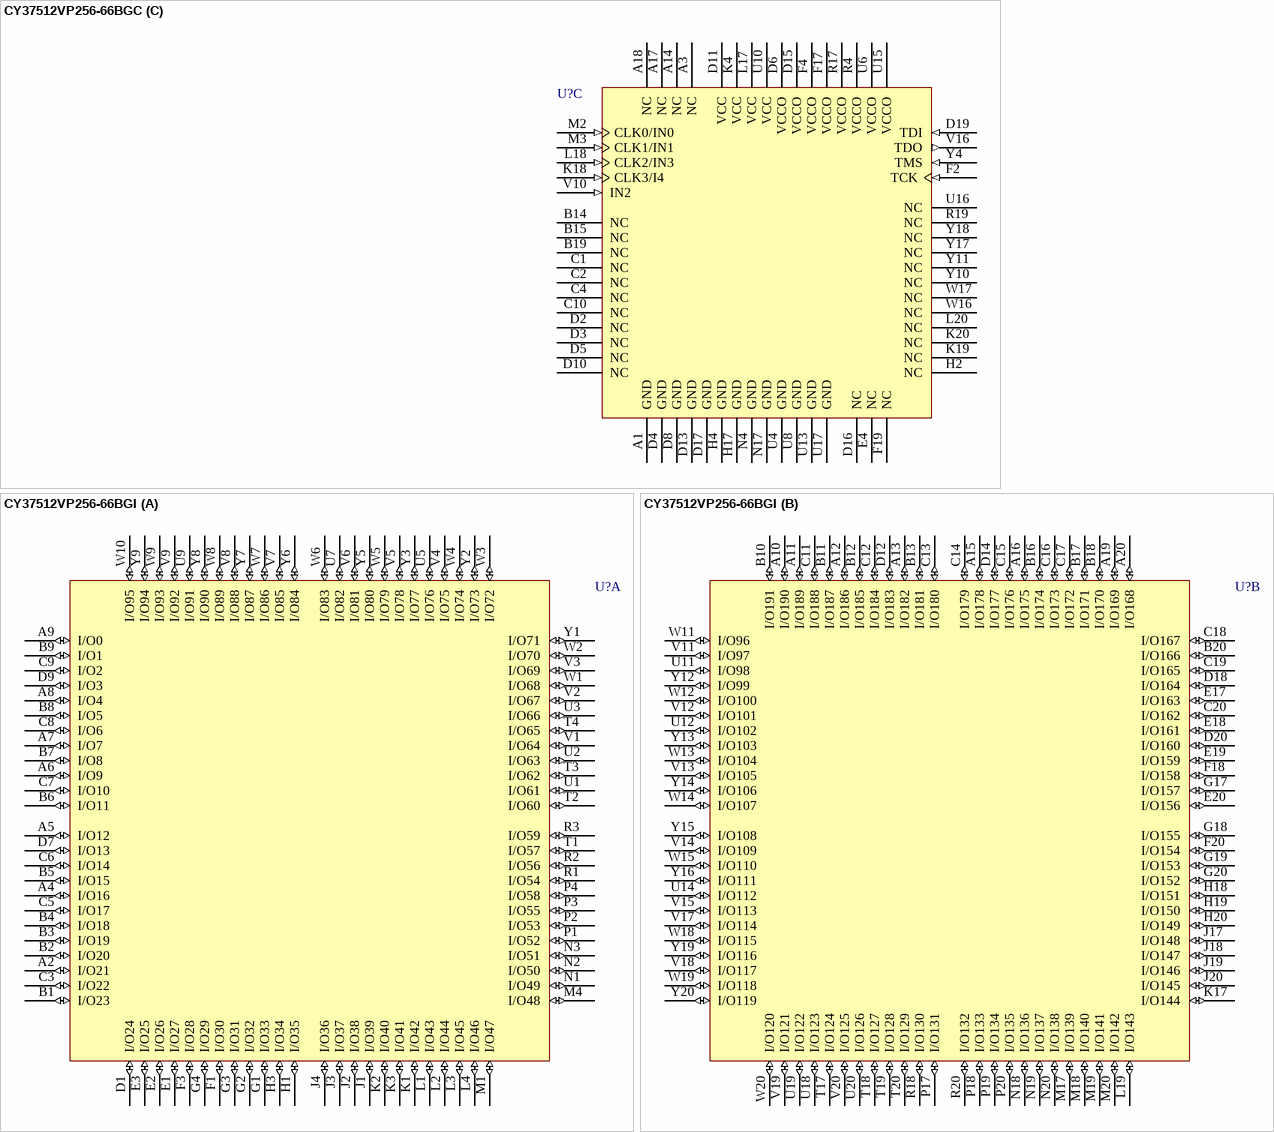
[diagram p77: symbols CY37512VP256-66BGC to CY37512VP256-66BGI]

## CY37512VP256-66BGC
designator U?
Ultra37000 3.3V, ISR High-Performance CPLD
footprint BG256 (BGA, 292-Leads, Body 27x27mm, Pitch 1.27mm)
3D model CY37512VP256-BG256 (292-Ball Ball Grid Array 1.27 mm Pitch)
part A pins: A2 I/O21 (io), A4 I/O16 (io), A5 I/O12 (io), A6 I/O9 (io), A7 I/O7 (io), A8 I/O4 (io), A9 I/O0 (io), B1 I/O23 (io), B2 I/O20 (io), B3 I/O19 (io), B4 I/O18 (io), B5 I/O15 (io), B6 I/O11 (io), B7 I/O8 (io), B8 I/O5 (io), B9 I/O1 (io), C3 I/O22 (io), C5 I/O17 (io), C6 I/O14 (io), C7 I/O10 (io), C8 I/O6 (io), C9 I/O2 (io), D1 I/O24 (io), D7 I/O13 (io), D9 I/O3 (io), E1 I/O27 (io), E2 I/O26 (io), E3 I/O25 (io), F1 I/O30 (io), F3 I/O28 (io), G1 I/O33 (io), G2 I/O32 (io), G3 I/O31 (io), G4 I/O29 (io), H1 I/O35 (io), H3 I/O34 (io), J1 I/O39 (io), J2 I/O38 (io), J3 I/O37 (io), J4 I/O36 (io), K1 I/O42 (io), K2 I/O40 (io), K3 I/O41 (io), L1 I/O43 (io), L2 I/O44 (io), L3 I/O45 (io), L4 I/O46 (io), M1 I/O47 (io), M4 I/O48 (io), N1 I/O49 (io), N2 I/O50 (io), N3 I/O51 (io), P1 I/O52 (io), P2 I/O53 (io), P3 I/O55 (io), P4 I/O58 (io), R1 I/O54 (io), R2 I/O56 (io), R3 I/O59 (io), T1 I/O57 (io), T2 I/O60 (io), T3 I/O62 (io), T4 I/O65 (io), U1 I/O61 (io), U2 I/O63 (io), U3 I/O66 (io), U5 I/O76 (io), U7 I/O82 (io), U9 I/O91 (io), V1 I/O64 (io), V2 I/O67 (io), V3 I/O69 (io), V4 I/O75 (io), V5 I/O78 (io), V6 I/O81 (io), V7 I/O85 (io), V8 I/O88 (io), V9 I/O92 (io), W1 I/O68 (io), W2 I/O70 (io), W3 I/O72 (io), W4 I/O74 (io), W5 I/O79 (io), W6 I/O83 (io), W7 I/O86 (io), W8 I/O89 (io), W9 I/O93 (io), W10 I/O95 (io), Y1 I/O71 (io), Y2 I/O73 (io), Y3 I/O77 (io), Y5 I/O80 (io), Y6 I/O84 (io), Y7 I/O87 (io), Y8 I/O90 (io), Y9 I/O94 (io)
part B pins: A10 I/O190 (io), A11 I/O189 (io), A12 I/O186 (io), A13 I/O182 (io), A15 I/O178 (io), A16 I/O175 (io), A19 I/O169 (io), A20 I/O168 (io), B10 I/O191 (io), B11 I/O187 (io), B12 I/O185 (io), B13 I/O181 (io), B16 I/O174 (io), B17 I/O171 (io), B18 I/O170 (io), B20 I/O166 (io), C11 I/O188 (io), C12 I/O184 (io), C13 I/O180 (io), C14 I/O179 (io), C15 I/O176 (io), C16 I/O173 (io), C17 I/O172 (io), C18 I/O167 (io), C19 I/O165 (io), C20 I/O162 (io), D12 I/O183 (io), D14 I/O177 (io), D18 I/O164 (io), D20 I/O160 (io), E17 I/O163 (io), E18 I/O161 (io), E19 I/O159 (io), E20 I/O156 (io), F18 I/O158 (io), F20 I/O154 (io), G17 I/O157 (io), G18 I/O155 (io), G19 I/O153 (io), G20 I/O152 (io), H18 I/O151 (io), H19 I/O150 (io), H20 I/O149 (io), J17 I/O148 (io), J18 I/O147 (io), J19 I/O146 (io), J20 I/O145 (io), K17 I/O144 (io), L19 I/O143 (io), M17 I/O139 (io), M18 I/O140 (io), M19 I/O141 (io), M20 I/O142 (io), N18 I/O136 (io), N19 I/O137 (io), N20 I/O138 (io), P17 I/O131 (io), P18 I/O133 (io), P19 I/O134 (io), P20 I/O135 (io), R18 I/O130 (io), R20 I/O132 (io), T17 I/O124 (io), T18 I/O127 (io), T19 I/O128 (io), T20 I/O129 (io), U11 I/O98 (io), U12 I/O102 (io), U14 I/O112 (io), U18 I/O123 (io), U19 I/O122 (io), U20 I/O126 (io), V11 I/O97 (io), V12 I/O101 (io), V13 I/O105 (io), V14 I/O109 (io), V15 I/O113 (io), V17 I/O114 (io), V18 I/O117 (io), V19 I/O121 (io), V20 I/O125 (io), W11 I/O96 (io), W12 I/O100 (io), W13 I/O104 (io), W14 I/O107 (io), W15 I/O110 (io), W18 I/O115 (io), W19 I/O118 (io), W20 I/O120 (io), Y12 I/O99 (io), Y13 I/O103 (io), Y14 I/O106 (io), Y15 I/O108 (io), Y16 I/O111 (io), Y19 I/O116 (io), Y20 I/O119 (io)
part C pins: A1 GND (power), A3 NC, A14 NC, A17 NC, A18 NC, B14 NC, B15 NC, B19 NC, C1 NC, C2 NC, C4 NC, C10 NC, D2 NC, D3 NC, D4 GND (power), D5 NC, D6 VCCO (power), D8 GND (power), D10 NC, D11 VCC (power), D13 GND (power), D15 VCCO (power), D16 NC, D17 GND (power), D19 TDI (in), E4 NC, F2 TCK (in), F4 VCCO (power), F17 VCCO (power), F19 NC, H2 NC, H4 GND (power), H17 GND (power), K4 VCC (power), K18 CLK3/I4 (in), K19 NC, K20 NC, L17 VCC (power), L18 CLK2/IN3 (in), L20 NC, M2 CLK0/IN0 (in), M3 CLK1/IN1 (in), N4 GND (power), N17 GND (power), R4 VCCO (power), R17 VCCO (power), R19 NC, U4 GND (power), U6 VCCO (power), U8 GND (power), U10 VCC (power), U13 GND (power), U15 VCCO (power), U16 NC, U17 GND (power), V10 IN2 (in), V16 TDO (out), W16 NC, W17 NC, Y4 TMS (in), Y10 NC, Y11 NC, Y17 NC, Y18 NC

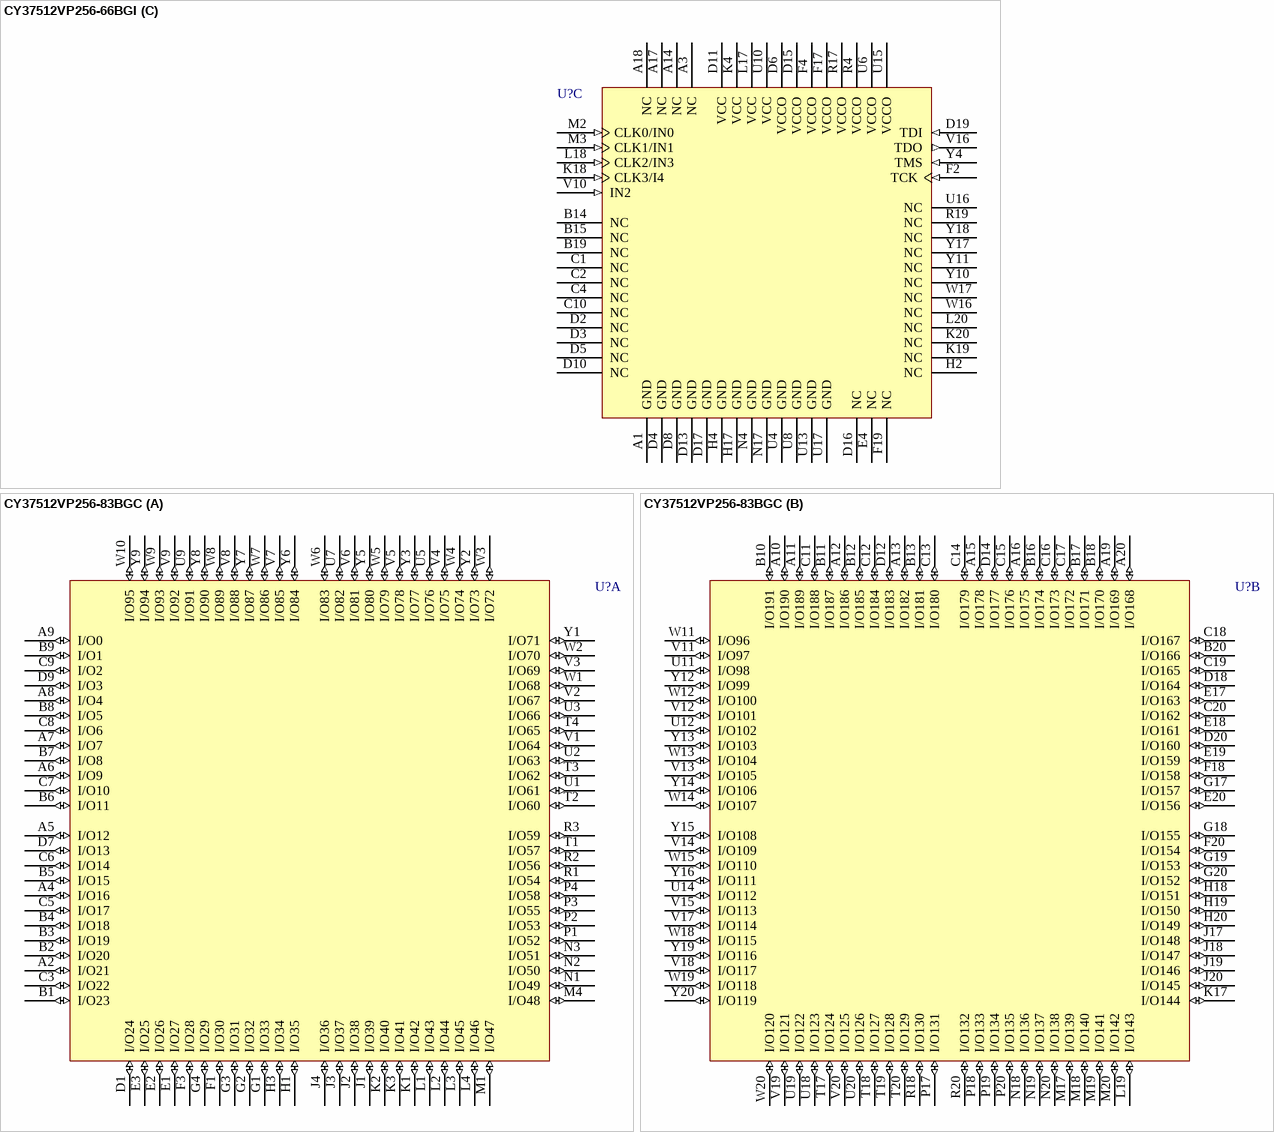
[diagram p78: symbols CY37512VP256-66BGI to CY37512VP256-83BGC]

## CY37512VP256-66BGI
designator U?
Ultra37000 3.3V, ISR High-Performance CPLD
footprint BG256 (BGA, 292-Leads, Body 27x27mm, Pitch 1.27mm)
3D model CY37512VP256-BG256 (292-Ball Ball Grid Array 1.27 mm Pitch)
part A pins: A2 I/O21 (io), A4 I/O16 (io), A5 I/O12 (io), A6 I/O9 (io), A7 I/O7 (io), A8 I/O4 (io), A9 I/O0 (io), B1 I/O23 (io), B2 I/O20 (io), B3 I/O19 (io), B4 I/O18 (io), B5 I/O15 (io), B6 I/O11 (io), B7 I/O8 (io), B8 I/O5 (io), B9 I/O1 (io), C3 I/O22 (io), C5 I/O17 (io), C6 I/O14 (io), C7 I/O10 (io), C8 I/O6 (io), C9 I/O2 (io), D1 I/O24 (io), D7 I/O13 (io), D9 I/O3 (io), E1 I/O27 (io), E2 I/O26 (io), E3 I/O25 (io), F1 I/O30 (io), F3 I/O28 (io), G1 I/O33 (io), G2 I/O32 (io), G3 I/O31 (io), G4 I/O29 (io), H1 I/O35 (io), H3 I/O34 (io), J1 I/O39 (io), J2 I/O38 (io), J3 I/O37 (io), J4 I/O36 (io), K1 I/O42 (io), K2 I/O40 (io), K3 I/O41 (io), L1 I/O43 (io), L2 I/O44 (io), L3 I/O45 (io), L4 I/O46 (io), M1 I/O47 (io), M4 I/O48 (io), N1 I/O49 (io), N2 I/O50 (io), N3 I/O51 (io), P1 I/O52 (io), P2 I/O53 (io), P3 I/O55 (io), P4 I/O58 (io), R1 I/O54 (io), R2 I/O56 (io), R3 I/O59 (io), T1 I/O57 (io), T2 I/O60 (io), T3 I/O62 (io), T4 I/O65 (io), U1 I/O61 (io), U2 I/O63 (io), U3 I/O66 (io), U5 I/O76 (io), U7 I/O82 (io), U9 I/O91 (io), V1 I/O64 (io), V2 I/O67 (io), V3 I/O69 (io), V4 I/O75 (io), V5 I/O78 (io), V6 I/O81 (io), V7 I/O85 (io), V8 I/O88 (io), V9 I/O92 (io), W1 I/O68 (io), W2 I/O70 (io), W3 I/O72 (io), W4 I/O74 (io), W5 I/O79 (io), W6 I/O83 (io), W7 I/O86 (io), W8 I/O89 (io), W9 I/O93 (io), W10 I/O95 (io), Y1 I/O71 (io), Y2 I/O73 (io), Y3 I/O77 (io), Y5 I/O80 (io), Y6 I/O84 (io), Y7 I/O87 (io), Y8 I/O90 (io), Y9 I/O94 (io)
part B pins: A10 I/O190 (io), A11 I/O189 (io), A12 I/O186 (io), A13 I/O182 (io), A15 I/O178 (io), A16 I/O175 (io), A19 I/O169 (io), A20 I/O168 (io), B10 I/O191 (io), B11 I/O187 (io), B12 I/O185 (io), B13 I/O181 (io), B16 I/O174 (io), B17 I/O171 (io), B18 I/O170 (io), B20 I/O166 (io), C11 I/O188 (io), C12 I/O184 (io), C13 I/O180 (io), C14 I/O179 (io), C15 I/O176 (io), C16 I/O173 (io), C17 I/O172 (io), C18 I/O167 (io), C19 I/O165 (io), C20 I/O162 (io), D12 I/O183 (io), D14 I/O177 (io), D18 I/O164 (io), D20 I/O160 (io), E17 I/O163 (io), E18 I/O161 (io), E19 I/O159 (io), E20 I/O156 (io), F18 I/O158 (io), F20 I/O154 (io), G17 I/O157 (io), G18 I/O155 (io), G19 I/O153 (io), G20 I/O152 (io), H18 I/O151 (io), H19 I/O150 (io), H20 I/O149 (io), J17 I/O148 (io), J18 I/O147 (io), J19 I/O146 (io), J20 I/O145 (io), K17 I/O144 (io), L19 I/O143 (io), M17 I/O139 (io), M18 I/O140 (io), M19 I/O141 (io), M20 I/O142 (io), N18 I/O136 (io), N19 I/O137 (io), N20 I/O138 (io), P17 I/O131 (io), P18 I/O133 (io), P19 I/O134 (io), P20 I/O135 (io), R18 I/O130 (io), R20 I/O132 (io), T17 I/O124 (io), T18 I/O127 (io), T19 I/O128 (io), T20 I/O129 (io), U11 I/O98 (io), U12 I/O102 (io), U14 I/O112 (io), U18 I/O123 (io), U19 I/O122 (io), U20 I/O126 (io), V11 I/O97 (io), V12 I/O101 (io), V13 I/O105 (io), V14 I/O109 (io), V15 I/O113 (io), V17 I/O114 (io), V18 I/O117 (io), V19 I/O121 (io), V20 I/O125 (io), W11 I/O96 (io), W12 I/O100 (io), W13 I/O104 (io), W14 I/O107 (io), W15 I/O110 (io), W18 I/O115 (io), W19 I/O118 (io), W20 I/O120 (io), Y12 I/O99 (io), Y13 I/O103 (io), Y14 I/O106 (io), Y15 I/O108 (io), Y16 I/O111 (io), Y19 I/O116 (io), Y20 I/O119 (io)
part C pins: A1 GND (power), A3 NC, A14 NC, A17 NC, A18 NC, B14 NC, B15 NC, B19 NC, C1 NC, C2 NC, C4 NC, C10 NC, D2 NC, D3 NC, D4 GND (power), D5 NC, D6 VCCO (power), D8 GND (power), D10 NC, D11 VCC (power), D13 GND (power), D15 VCCO (power), D16 NC, D17 GND (power), D19 TDI (in), E4 NC, F2 TCK (in), F4 VCCO (power), F17 VCCO (power), F19 NC, H2 NC, H4 GND (power), H17 GND (power), K4 VCC (power), K18 CLK3/I4 (in), K19 NC, K20 NC, L17 VCC (power), L18 CLK2/IN3 (in), L20 NC, M2 CLK0/IN0 (in), M3 CLK1/IN1 (in), N4 GND (power), N17 GND (power), R4 VCCO (power), R17 VCCO (power), R19 NC, U4 GND (power), U6 VCCO (power), U8 GND (power), U10 VCC (power), U13 GND (power), U15 VCCO (power), U16 NC, U17 GND (power), V10 IN2 (in), V16 TDO (out), W16 NC, W17 NC, Y4 TMS (in), Y10 NC, Y11 NC, Y17 NC, Y18 NC

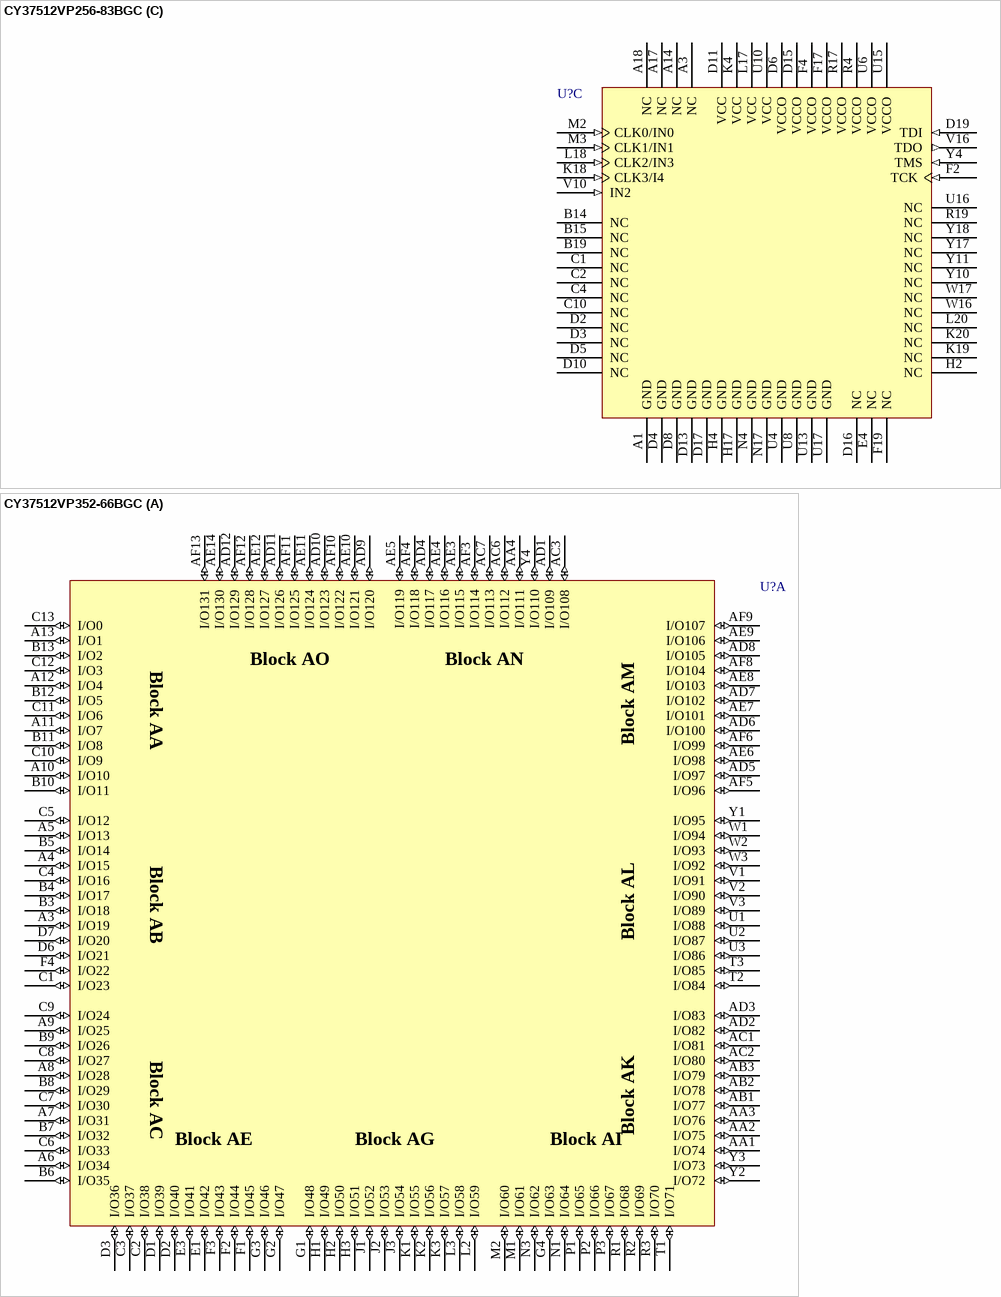
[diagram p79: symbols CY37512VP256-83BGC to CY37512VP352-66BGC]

## CY37512VP256-83BGC
designator U?
Ultra37000 3.3V, ISR High-Performance CPLD
footprint BG256 (BGA, 292-Leads, Body 27x27mm, Pitch 1.27mm)
3D model CY37512VP256-BG256 (292-Ball Ball Grid Array 1.27 mm Pitch)
part A pins: A2 I/O21 (io), A4 I/O16 (io), A5 I/O12 (io), A6 I/O9 (io), A7 I/O7 (io), A8 I/O4 (io), A9 I/O0 (io), B1 I/O23 (io), B2 I/O20 (io), B3 I/O19 (io), B4 I/O18 (io), B5 I/O15 (io), B6 I/O11 (io), B7 I/O8 (io), B8 I/O5 (io), B9 I/O1 (io), C3 I/O22 (io), C5 I/O17 (io), C6 I/O14 (io), C7 I/O10 (io), C8 I/O6 (io), C9 I/O2 (io), D1 I/O24 (io), D7 I/O13 (io), D9 I/O3 (io), E1 I/O27 (io), E2 I/O26 (io), E3 I/O25 (io), F1 I/O30 (io), F3 I/O28 (io), G1 I/O33 (io), G2 I/O32 (io), G3 I/O31 (io), G4 I/O29 (io), H1 I/O35 (io), H3 I/O34 (io), J1 I/O39 (io), J2 I/O38 (io), J3 I/O37 (io), J4 I/O36 (io), K1 I/O42 (io), K2 I/O40 (io), K3 I/O41 (io), L1 I/O43 (io), L2 I/O44 (io), L3 I/O45 (io), L4 I/O46 (io), M1 I/O47 (io), M4 I/O48 (io), N1 I/O49 (io), N2 I/O50 (io), N3 I/O51 (io), P1 I/O52 (io), P2 I/O53 (io), P3 I/O55 (io), P4 I/O58 (io), R1 I/O54 (io), R2 I/O56 (io), R3 I/O59 (io), T1 I/O57 (io), T2 I/O60 (io), T3 I/O62 (io), T4 I/O65 (io), U1 I/O61 (io), U2 I/O63 (io), U3 I/O66 (io), U5 I/O76 (io), U7 I/O82 (io), U9 I/O91 (io), V1 I/O64 (io), V2 I/O67 (io), V3 I/O69 (io), V4 I/O75 (io), V5 I/O78 (io), V6 I/O81 (io), V7 I/O85 (io), V8 I/O88 (io), V9 I/O92 (io), W1 I/O68 (io), W2 I/O70 (io), W3 I/O72 (io), W4 I/O74 (io), W5 I/O79 (io), W6 I/O83 (io), W7 I/O86 (io), W8 I/O89 (io), W9 I/O93 (io), W10 I/O95 (io), Y1 I/O71 (io), Y2 I/O73 (io), Y3 I/O77 (io), Y5 I/O80 (io), Y6 I/O84 (io), Y7 I/O87 (io), Y8 I/O90 (io), Y9 I/O94 (io)
part B pins: A10 I/O190 (io), A11 I/O189 (io), A12 I/O186 (io), A13 I/O182 (io), A15 I/O178 (io), A16 I/O175 (io), A19 I/O169 (io), A20 I/O168 (io), B10 I/O191 (io), B11 I/O187 (io), B12 I/O185 (io), B13 I/O181 (io), B16 I/O174 (io), B17 I/O171 (io), B18 I/O170 (io), B20 I/O166 (io), C11 I/O188 (io), C12 I/O184 (io), C13 I/O180 (io), C14 I/O179 (io), C15 I/O176 (io), C16 I/O173 (io), C17 I/O172 (io), C18 I/O167 (io), C19 I/O165 (io), C20 I/O162 (io), D12 I/O183 (io), D14 I/O177 (io), D18 I/O164 (io), D20 I/O160 (io), E17 I/O163 (io), E18 I/O161 (io), E19 I/O159 (io), E20 I/O156 (io), F18 I/O158 (io), F20 I/O154 (io), G17 I/O157 (io), G18 I/O155 (io), G19 I/O153 (io), G20 I/O152 (io), H18 I/O151 (io), H19 I/O150 (io), H20 I/O149 (io), J17 I/O148 (io), J18 I/O147 (io), J19 I/O146 (io), J20 I/O145 (io), K17 I/O144 (io), L19 I/O143 (io), M17 I/O139 (io), M18 I/O140 (io), M19 I/O141 (io), M20 I/O142 (io), N18 I/O136 (io), N19 I/O137 (io), N20 I/O138 (io), P17 I/O131 (io), P18 I/O133 (io), P19 I/O134 (io), P20 I/O135 (io), R18 I/O130 (io), R20 I/O132 (io), T17 I/O124 (io), T18 I/O127 (io), T19 I/O128 (io), T20 I/O129 (io), U11 I/O98 (io), U12 I/O102 (io), U14 I/O112 (io), U18 I/O123 (io), U19 I/O122 (io), U20 I/O126 (io), V11 I/O97 (io), V12 I/O101 (io), V13 I/O105 (io), V14 I/O109 (io), V15 I/O113 (io), V17 I/O114 (io), V18 I/O117 (io), V19 I/O121 (io), V20 I/O125 (io), W11 I/O96 (io), W12 I/O100 (io), W13 I/O104 (io), W14 I/O107 (io), W15 I/O110 (io), W18 I/O115 (io), W19 I/O118 (io), W20 I/O120 (io), Y12 I/O99 (io), Y13 I/O103 (io), Y14 I/O106 (io), Y15 I/O108 (io), Y16 I/O111 (io), Y19 I/O116 (io), Y20 I/O119 (io)
part C pins: A1 GND (power), A3 NC, A14 NC, A17 NC, A18 NC, B14 NC, B15 NC, B19 NC, C1 NC, C2 NC, C4 NC, C10 NC, D2 NC, D3 NC, D4 GND (power), D5 NC, D6 VCCO (power), D8 GND (power), D10 NC, D11 VCC (power), D13 GND (power), D15 VCCO (power), D16 NC, D17 GND (power), D19 TDI (in), E4 NC, F2 TCK (in), F4 VCCO (power), F17 VCCO (power), F19 NC, H2 NC, H4 GND (power), H17 GND (power), K4 VCC (power), K18 CLK3/I4 (in), K19 NC, K20 NC, L17 VCC (power), L18 CLK2/IN3 (in), L20 NC, M2 CLK0/IN0 (in), M3 CLK1/IN1 (in), N4 GND (power), N17 GND (power), R4 VCCO (power), R17 VCCO (power), R19 NC, U4 GND (power), U6 VCCO (power), U8 GND (power), U10 VCC (power), U13 GND (power), U15 VCCO (power), U16 NC, U17 GND (power), V10 IN2 (in), V16 TDO (out), W16 NC, W17 NC, Y4 TMS (in), Y10 NC, Y11 NC, Y17 NC, Y18 NC

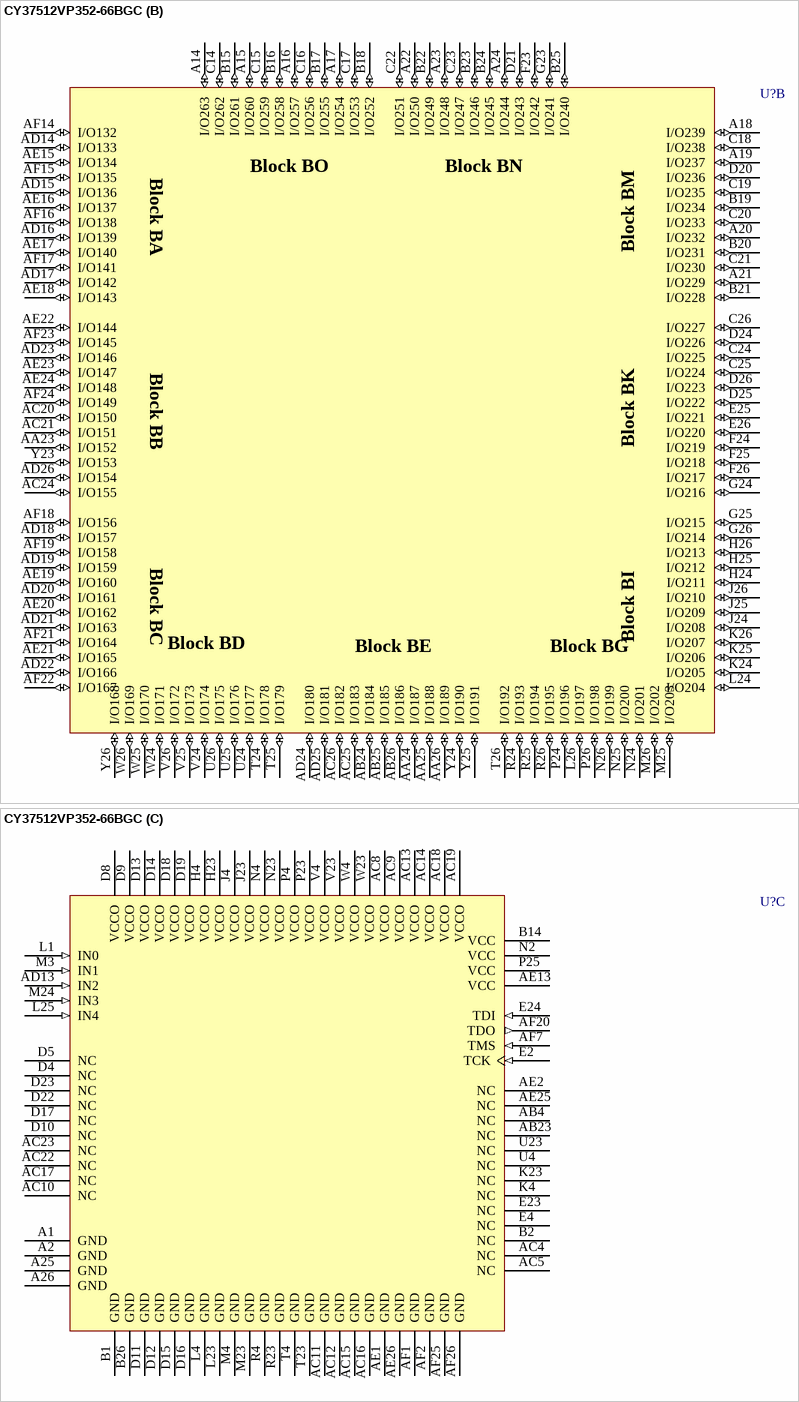
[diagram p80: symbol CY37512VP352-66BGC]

## CY37512VP352-66BGC
designator U?
Ultra37000 3.3V, ISR High-Performance CPLD
footprint BG352 (BGA, 388-Leads, Body 35x35mm, Pitch 1.27mm)
3D model CY37512VP352-BG352 (388-Ball Ball Grid Array 1.27 mm Pitch)
part A pins: A3 I/O19 (io), A4 I/O15 (io), A5 I/O13 (io), A6 I/O34 (io), A7 I/O31 (io), A8 I/O28 (io), A9 I/O25 (io), A10 I/O10 (io), A11 I/O7 (io), A12 I/O4 (io), A13 I/O1 (io), AA1 I/O74 (io), AA2 I/O75 (io), AA3 I/O76 (io), AA4 I/O111 (io), AB1 I/O77 (io), AB2 I/O78 (io), AB3 I/O79 (io), AC1 I/O81 (io), AC2 I/O80 (io), AC3 I/O108 (io), AC6 I/O112 (io), AC7 I/O113 (io), AD1 I/O109 (io), AD2 I/O82 (io), AD3 I/O83 (io), AD4 I/O117 (io), AD5 I/O97 (io), AD6 I/O100 (io), AD7 I/O102 (io), AD8 I/O105 (io), AD9 I/O120 (io), AD10 I/O123 (io), AD11 I/O126 (io), AD12 I/O129 (io), AE3 I/O115 (io), AE4 I/O116 (io), AE5 I/O119 (io), AE6 I/O98 (io), AE7 I/O101 (io), AE8 I/O103 (io), AE9 I/O106 (io), AE10 I/O121 (io), AE11 I/O124 (io), AE12 I/O127 (io), AE14 I/O130 (io), AF3 I/O114 (io), AF4 I/O118 (io), AF5 I/O96 (io), AF6 I/O99 (io), AF8 I/O104 (io), AF9 I/O107 (io), AF10 I/O122 (io), AF11 I/O125 (io), AF12 I/O128 (io), AF13 I/O131 (io), B3 I/O18 (io), B4 I/O17 (io), B5 I/O14 (io), B6 I/O35 (io), B7 I/O32 (io), B8 I/O29 (io), B9 I/O26 (io), B10 I/O11 (io), B11 I/O8 (io), B12 I/O5 (io), B13 I/O2 (io), C1 I/O23 (io), C2 I/O38 (io), C3 I/O37 (io), C4 I/O16 (io), C5 I/O12 (io), C6 I/O33 (io), C7 I/O30 (io), C8 I/O27 (io), C9 I/O24 (io), C10 I/O9 (io), C11 I/O6 (io), C12 I/O3 (io), C13 I/O0 (io), D1 I/O39 (io), D2 I/O40 (io), D3 I/O36 (io), D6 I/O21 (io), D7 I/O20 (io), E1 I/O42 (io), E3 I/O41 (io), F1 I/O45 (io), F2 I/O44 (io), F3 I/O43 (io), F4 I/O22 (io), G1 I/O48 (io), G2 I/O47 (io), G3 I/O46 (io), G4 I/O63 (io), H1 I/O49 (io), H2 I/O50 (io), H3 I/O51 (io), J1 I/O52 (io), J2 I/O53 (io), J3 I/O54 (io), K1 I/O55 (io), K2 I/O56 (io), K3 I/O57 (io), L2 I/O59 (io), L3 I/O58 (io), M1 I/O61 (io), M2 I/O60 (io), N1 I/O64 (io), N3 I/O62 (io), P1 I/O65 (io), P2 I/O66 (io), P3 I/O67 (io), R1 I/O68 (io), R2 I/O69 (io), R3 I/O70 (io), T1 I/O71 (io), T2 I/O84 (io), T3 I/O85 (io), U1 I/O88 (io), U2 I/O87 (io), U3 I/O86 (io), V1 I/O91 (io), V2 I/O90 (io), V3 I/O89 (io), W1 I/O94 (io), W2 I/O93 (io), W3 I/O92 (io), Y1 I/O95 (io), Y2 I/O72 (io), Y3 I/O73 (io), Y4 I/O110 (io)
part B pins: A14 I/O263 (io), A15 I/O260 (io), A16 I/O257 (io), A17 I/O254 (io), A18 I/O239 (io), A19 I/O237 (io), A20 I/O232 (io), A21 I/O229 (io), A22 I/O250 (io), A23 I/O248 (io), A24 I/O244 (io), AA23 I/O152 (io), AA24 I/O187 (io), AA25 I/O188 (io), AA26 I/O189 (io), AB24 I/O184 (io), AB25 I/O185 (io), AB26 I/O186 (io), AC20 I/O150 (io), AC21 I/O151 (io), AC24 I/O155 (io), AC25 I/O183 (io), AC26 I/O182 (io), AD14 I/O133 (io), AD15 I/O136 (io), AD16 I/O139 (io), AD17 I/O142 (io), AD18 I/O157 (io), AD19 I/O159 (io), AD20 I/O161 (io), AD21 I/O163 (io), AD22 I/O166 (io), AD23 I/O146 (io), AD24 I/O180 (io), AD25 I/O181 (io), AD26 I/O154 (io), AE15 I/O134 (io), AE16 I/O137 (io), AE17 I/O140 (io), AE18 I/O143 (io), AE19 I/O160 (io), AE20 I/O162 (io), AE21 I/O165 (io), AE22 I/O144 (io), AE23 I/O147 (io), AE24 I/O148 (io), AF14 I/O132 (io), AF15 I/O135 (io), AF16 I/O138 (io), AF17 I/O141 (io), AF18 I/O156 (io), AF19 I/O158 (io), AF21 I/O164 (io), AF22 I/O167 (io), AF23 I/O145 (io), AF24 I/O149 (io), B15 I/O261 (io), B16 I/O258 (io), B17 I/O255 (io), B18 I/O252 (io), B19 I/O234 (io), B20 I/O231 (io), B21 I/O228 (io), B22 I/O249 (io), B23 I/O246 (io), B24 I/O245 (io), B25 I/O240 (io), C14 I/O262 (io), C15 I/O259 (io), C16 I/O256 (io), C17 I/O253 (io), C18 I/O238 (io), C19 I/O235 (io), C20 I/O233 (io), C21 I/O230 (io), C22 I/O251 (io), C23 I/O247 (io), C24 I/O225 (io), C25 I/O224 (io), C26 I/O227 (io), D20 I/O236 (io), D21 I/O243 (io), D24 I/O226 (io), D25 I/O222 (io), D26 I/O223 (io), E25 I/O221 (io), E26 I/O220 (io), F23 I/O242 (io), F24 I/O219 (io), F25 I/O218 (io), F26 I/O217 (io), G23 I/O241 (io), G24 I/O216 (io), G25 I/O215 (io), G26 I/O214 (io), H24 I/O211 (io), H25 I/O212 (io), H26 I/O213 (io), J24 I/O208 (io), J25 I/O209 (io), J26 I/O210 (io), K24 I/O205 (io), K25 I/O206 (io), K26 I/O207 (io), L24 I/O204 (io), L26 I/O197 (io), M25 I/O203 (io), M26 I/O202 (io), N24 I/O201 (io), N25 I/O200 (io), N26 I/O199 (io), P24 I/O196 (io), P26 I/O198 (io), R24 I/O193 (io), R25 I/O194 (io), R26 I/O195 (io), T24 I/O178 (io), T25 I/O179 (io), T26 I/O192 (io), U24 I/O177 (io), U25 I/O176 (io), U26 I/O175 (io), V24 I/O174 (io), V25 I/O173 (io), V26 I/O172 (io), W24 I/O171 (io), W25 I/O170 (io), W26 I/O169 (io), Y23 I/O153 (io), Y24 I/O190 (io), Y25 I/O191 (io), Y26 I/O168 (io)
part C pins: A1 GND (power), A2 GND (power), A25 GND (power), A26 GND (power), AB4 NC, AB23 NC, AC4 NC, AC5 NC, AC8 VCCO (power), AC9 VCCO (power), AC10 NC, AC11 GND (power), AC12 GND (power), AC13 VCCO (power), AC14 VCCO (power), AC15 GND (power), AC16 GND (power), AC17 NC, AC18 VCCO (power), AC19 VCCO (power), AC22 NC, AC23 NC, AD13 IN2 (in), AE1 GND (power), AE2 NC, AE13 VCC (power), AE25 NC, AE26 GND (power), AF1 GND (power), AF2 GND (power), AF7 TMS (in), AF20 TDO (out), AF25 GND (power), AF26 GND (power), B1 GND (power), B2 NC, B14 VCC (power), B26 GND (power), D4 NC, D5 NC, D8 VCCO (power), D9 VCCO (power), D10 NC, D11 GND (power), D12 GND (power), D13 VCCO (power), D14 VCCO (power), D15 GND (power), D16 GND (power), D17 NC, D18 VCCO (power), D19 VCCO (power), D22 NC, D23 NC, E2 TCK (in), E4 NC, E23 NC, E24 TDI (in), H4 VCCO (power), H23 VCCO (power), J4 VCCO (power), J23 VCCO (power), K4 NC, K23 NC, L1 IN0 (in), L4 GND (power), L23 GND (power), L25 IN4 (in), M3 IN1 (in), M4 GND (power), M23 GND (power), M24 IN3 (in), N2 VCC (power), N4 VCCO (power), N23 VCCO (power), P4 VCCO (power), P23 VCCO (power), P25 VCC (power), R4 GND (power), R23 GND (power), T4 GND (power), T23 GND (power), U4 NC, U23 NC, V4 VCCO (power), V23 VCCO (power), W4 VCCO (power), W23 VCCO (power)

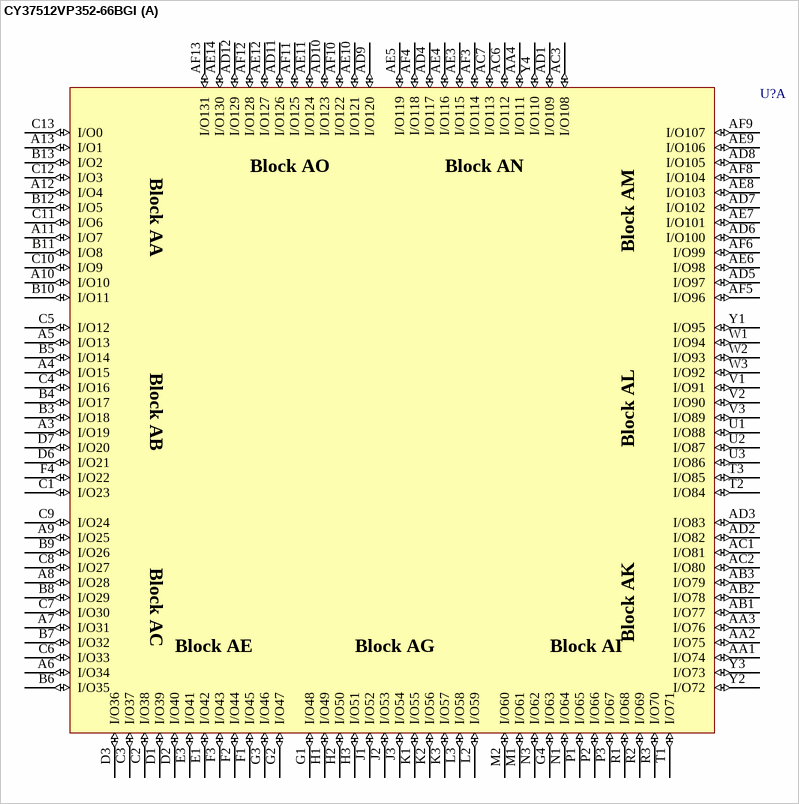
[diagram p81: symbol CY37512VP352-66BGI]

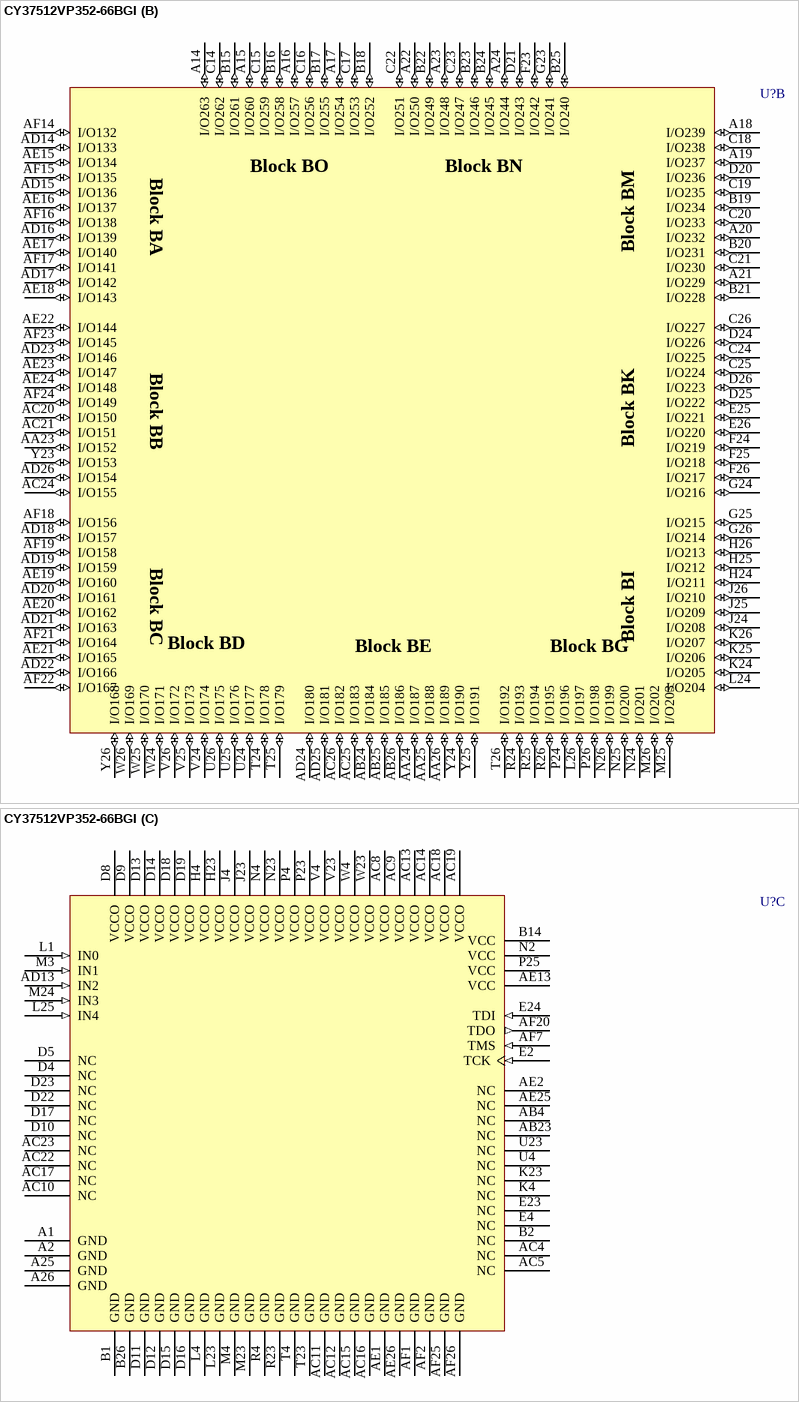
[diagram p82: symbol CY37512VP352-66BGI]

## CY37512VP352-66BGI
designator U?
Ultra37000 3.3V, ISR High-Performance CPLD
footprint BG352 (BGA, 388-Leads, Body 35x35mm, Pitch 1.27mm)
3D model CY37512VP352-BG352 (388-Ball Ball Grid Array 1.27 mm Pitch)
part A pins: A3 I/O19 (io), A4 I/O15 (io), A5 I/O13 (io), A6 I/O34 (io), A7 I/O31 (io), A8 I/O28 (io), A9 I/O25 (io), A10 I/O10 (io), A11 I/O7 (io), A12 I/O4 (io), A13 I/O1 (io), AA1 I/O74 (io), AA2 I/O75 (io), AA3 I/O76 (io), AA4 I/O111 (io), AB1 I/O77 (io), AB2 I/O78 (io), AB3 I/O79 (io), AC1 I/O81 (io), AC2 I/O80 (io), AC3 I/O108 (io), AC6 I/O112 (io), AC7 I/O113 (io), AD1 I/O109 (io), AD2 I/O82 (io), AD3 I/O83 (io), AD4 I/O117 (io), AD5 I/O97 (io), AD6 I/O100 (io), AD7 I/O102 (io), AD8 I/O105 (io), AD9 I/O120 (io), AD10 I/O123 (io), AD11 I/O126 (io), AD12 I/O129 (io), AE3 I/O115 (io), AE4 I/O116 (io), AE5 I/O119 (io), AE6 I/O98 (io), AE7 I/O101 (io), AE8 I/O103 (io), AE9 I/O106 (io), AE10 I/O121 (io), AE11 I/O124 (io), AE12 I/O127 (io), AE14 I/O130 (io), AF3 I/O114 (io), AF4 I/O118 (io), AF5 I/O96 (io), AF6 I/O99 (io), AF8 I/O104 (io), AF9 I/O107 (io), AF10 I/O122 (io), AF11 I/O125 (io), AF12 I/O128 (io), AF13 I/O131 (io), B3 I/O18 (io), B4 I/O17 (io), B5 I/O14 (io), B6 I/O35 (io), B7 I/O32 (io), B8 I/O29 (io), B9 I/O26 (io), B10 I/O11 (io), B11 I/O8 (io), B12 I/O5 (io), B13 I/O2 (io), C1 I/O23 (io), C2 I/O38 (io), C3 I/O37 (io), C4 I/O16 (io), C5 I/O12 (io), C6 I/O33 (io), C7 I/O30 (io), C8 I/O27 (io), C9 I/O24 (io), C10 I/O9 (io), C11 I/O6 (io), C12 I/O3 (io), C13 I/O0 (io), D1 I/O39 (io), D2 I/O40 (io), D3 I/O36 (io), D6 I/O21 (io), D7 I/O20 (io), E1 I/O42 (io), E3 I/O41 (io), F1 I/O45 (io), F2 I/O44 (io), F3 I/O43 (io), F4 I/O22 (io), G1 I/O48 (io), G2 I/O47 (io), G3 I/O46 (io), G4 I/O63 (io), H1 I/O49 (io), H2 I/O50 (io), H3 I/O51 (io), J1 I/O52 (io), J2 I/O53 (io), J3 I/O54 (io), K1 I/O55 (io), K2 I/O56 (io), K3 I/O57 (io), L2 I/O59 (io), L3 I/O58 (io), M1 I/O61 (io), M2 I/O60 (io), N1 I/O64 (io), N3 I/O62 (io), P1 I/O65 (io), P2 I/O66 (io), P3 I/O67 (io), R1 I/O68 (io), R2 I/O69 (io), R3 I/O70 (io), T1 I/O71 (io), T2 I/O84 (io), T3 I/O85 (io), U1 I/O88 (io), U2 I/O87 (io), U3 I/O86 (io), V1 I/O91 (io), V2 I/O90 (io), V3 I/O89 (io), W1 I/O94 (io), W2 I/O93 (io), W3 I/O92 (io), Y1 I/O95 (io), Y2 I/O72 (io), Y3 I/O73 (io), Y4 I/O110 (io)
part B pins: A14 I/O263 (io), A15 I/O260 (io), A16 I/O257 (io), A17 I/O254 (io), A18 I/O239 (io), A19 I/O237 (io), A20 I/O232 (io), A21 I/O229 (io), A22 I/O250 (io), A23 I/O248 (io), A24 I/O244 (io), AA23 I/O152 (io), AA24 I/O187 (io), AA25 I/O188 (io), AA26 I/O189 (io), AB24 I/O184 (io), AB25 I/O185 (io), AB26 I/O186 (io), AC20 I/O150 (io), AC21 I/O151 (io), AC24 I/O155 (io), AC25 I/O183 (io), AC26 I/O182 (io), AD14 I/O133 (io), AD15 I/O136 (io), AD16 I/O139 (io), AD17 I/O142 (io), AD18 I/O157 (io), AD19 I/O159 (io), AD20 I/O161 (io), AD21 I/O163 (io), AD22 I/O166 (io), AD23 I/O146 (io), AD24 I/O180 (io), AD25 I/O181 (io), AD26 I/O154 (io), AE15 I/O134 (io), AE16 I/O137 (io), AE17 I/O140 (io), AE18 I/O143 (io), AE19 I/O160 (io), AE20 I/O162 (io), AE21 I/O165 (io), AE22 I/O144 (io), AE23 I/O147 (io), AE24 I/O148 (io), AF14 I/O132 (io), AF15 I/O135 (io), AF16 I/O138 (io), AF17 I/O141 (io), AF18 I/O156 (io), AF19 I/O158 (io), AF21 I/O164 (io), AF22 I/O167 (io), AF23 I/O145 (io), AF24 I/O149 (io), B15 I/O261 (io), B16 I/O258 (io), B17 I/O255 (io), B18 I/O252 (io), B19 I/O234 (io), B20 I/O231 (io), B21 I/O228 (io), B22 I/O249 (io), B23 I/O246 (io), B24 I/O245 (io), B25 I/O240 (io), C14 I/O262 (io), C15 I/O259 (io), C16 I/O256 (io), C17 I/O253 (io), C18 I/O238 (io), C19 I/O235 (io), C20 I/O233 (io), C21 I/O230 (io), C22 I/O251 (io), C23 I/O247 (io), C24 I/O225 (io), C25 I/O224 (io), C26 I/O227 (io), D20 I/O236 (io), D21 I/O243 (io), D24 I/O226 (io), D25 I/O222 (io), D26 I/O223 (io), E25 I/O221 (io), E26 I/O220 (io), F23 I/O242 (io), F24 I/O219 (io), F25 I/O218 (io), F26 I/O217 (io), G23 I/O241 (io), G24 I/O216 (io), G25 I/O215 (io), G26 I/O214 (io), H24 I/O211 (io), H25 I/O212 (io), H26 I/O213 (io), J24 I/O208 (io), J25 I/O209 (io), J26 I/O210 (io), K24 I/O205 (io), K25 I/O206 (io), K26 I/O207 (io), L24 I/O204 (io), L26 I/O197 (io), M25 I/O203 (io), M26 I/O202 (io), N24 I/O201 (io), N25 I/O200 (io), N26 I/O199 (io), P24 I/O196 (io), P26 I/O198 (io), R24 I/O193 (io), R25 I/O194 (io), R26 I/O195 (io), T24 I/O178 (io), T25 I/O179 (io), T26 I/O192 (io), U24 I/O177 (io), U25 I/O176 (io), U26 I/O175 (io), V24 I/O174 (io), V25 I/O173 (io), V26 I/O172 (io), W24 I/O171 (io), W25 I/O170 (io), W26 I/O169 (io), Y23 I/O153 (io), Y24 I/O190 (io), Y25 I/O191 (io), Y26 I/O168 (io)
part C pins: A1 GND (power), A2 GND (power), A25 GND (power), A26 GND (power), AB4 NC, AB23 NC, AC4 NC, AC5 NC, AC8 VCCO (power), AC9 VCCO (power), AC10 NC, AC11 GND (power), AC12 GND (power), AC13 VCCO (power), AC14 VCCO (power), AC15 GND (power), AC16 GND (power), AC17 NC, AC18 VCCO (power), AC19 VCCO (power), AC22 NC, AC23 NC, AD13 IN2 (in), AE1 GND (power), AE2 NC, AE13 VCC (power), AE25 NC, AE26 GND (power), AF1 GND (power), AF2 GND (power), AF7 TMS (in), AF20 TDO (out), AF25 GND (power), AF26 GND (power), B1 GND (power), B2 NC, B14 VCC (power), B26 GND (power), D4 NC, D5 NC, D8 VCCO (power), D9 VCCO (power), D10 NC, D11 GND (power), D12 GND (power), D13 VCCO (power), D14 VCCO (power), D15 GND (power), D16 GND (power), D17 NC, D18 VCCO (power), D19 VCCO (power), D22 NC, D23 NC, E2 TCK (in), E4 NC, E23 NC, E24 TDI (in), H4 VCCO (power), H23 VCCO (power), J4 VCCO (power), J23 VCCO (power), K4 NC, K23 NC, L1 IN0 (in), L4 GND (power), L23 GND (power), L25 IN4 (in), M3 IN1 (in), M4 GND (power), M23 GND (power), M24 IN3 (in), N2 VCC (power), N4 VCCO (power), N23 VCCO (power), P4 VCCO (power), P23 VCCO (power), P25 VCC (power), R4 GND (power), R23 GND (power), T4 GND (power), T23 GND (power), U4 NC, U23 NC, V4 VCCO (power), V23 VCCO (power), W4 VCCO (power), W23 VCCO (power)

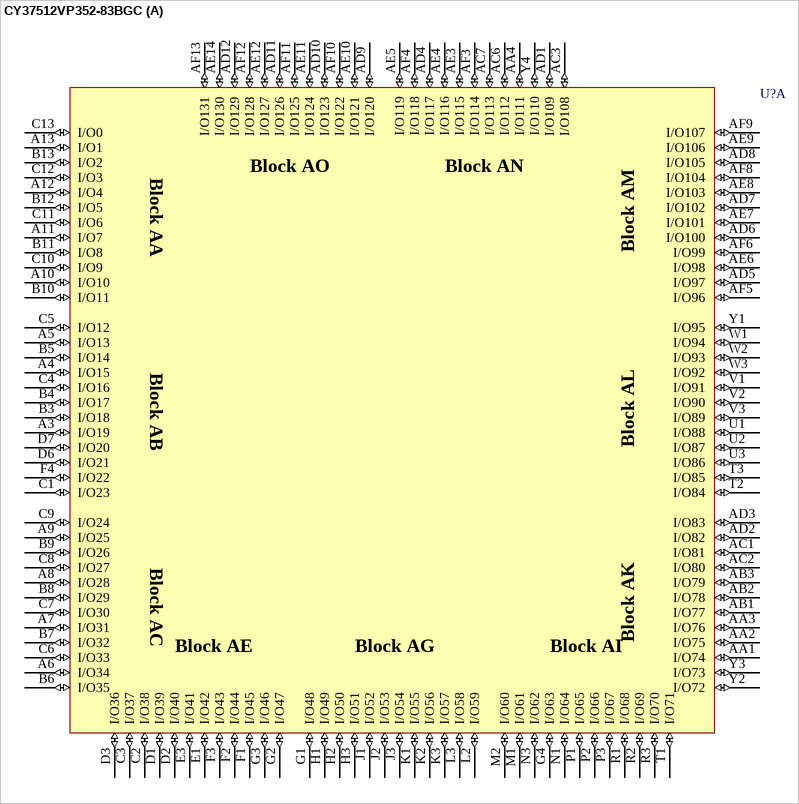
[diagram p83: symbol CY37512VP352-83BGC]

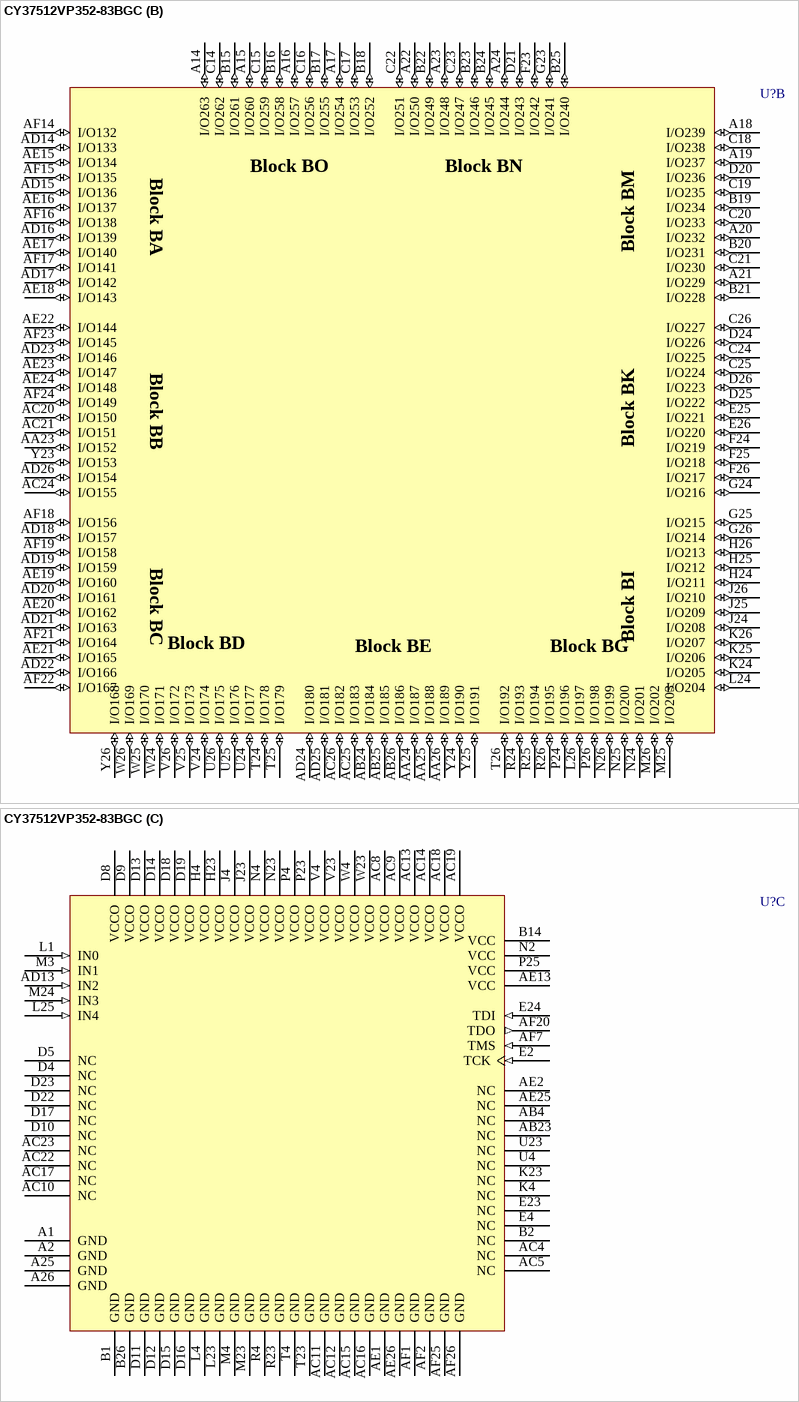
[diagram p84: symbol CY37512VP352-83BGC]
